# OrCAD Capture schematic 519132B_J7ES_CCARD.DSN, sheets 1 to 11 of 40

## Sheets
1 01.TITLE PAGE: title: J7ES CCARD; rev: A1; company: TEXAS INSTRUMENTS INCORPORATED; note: 519132; note: TIDEP-01020; note: Preliminary Information - Subject to change
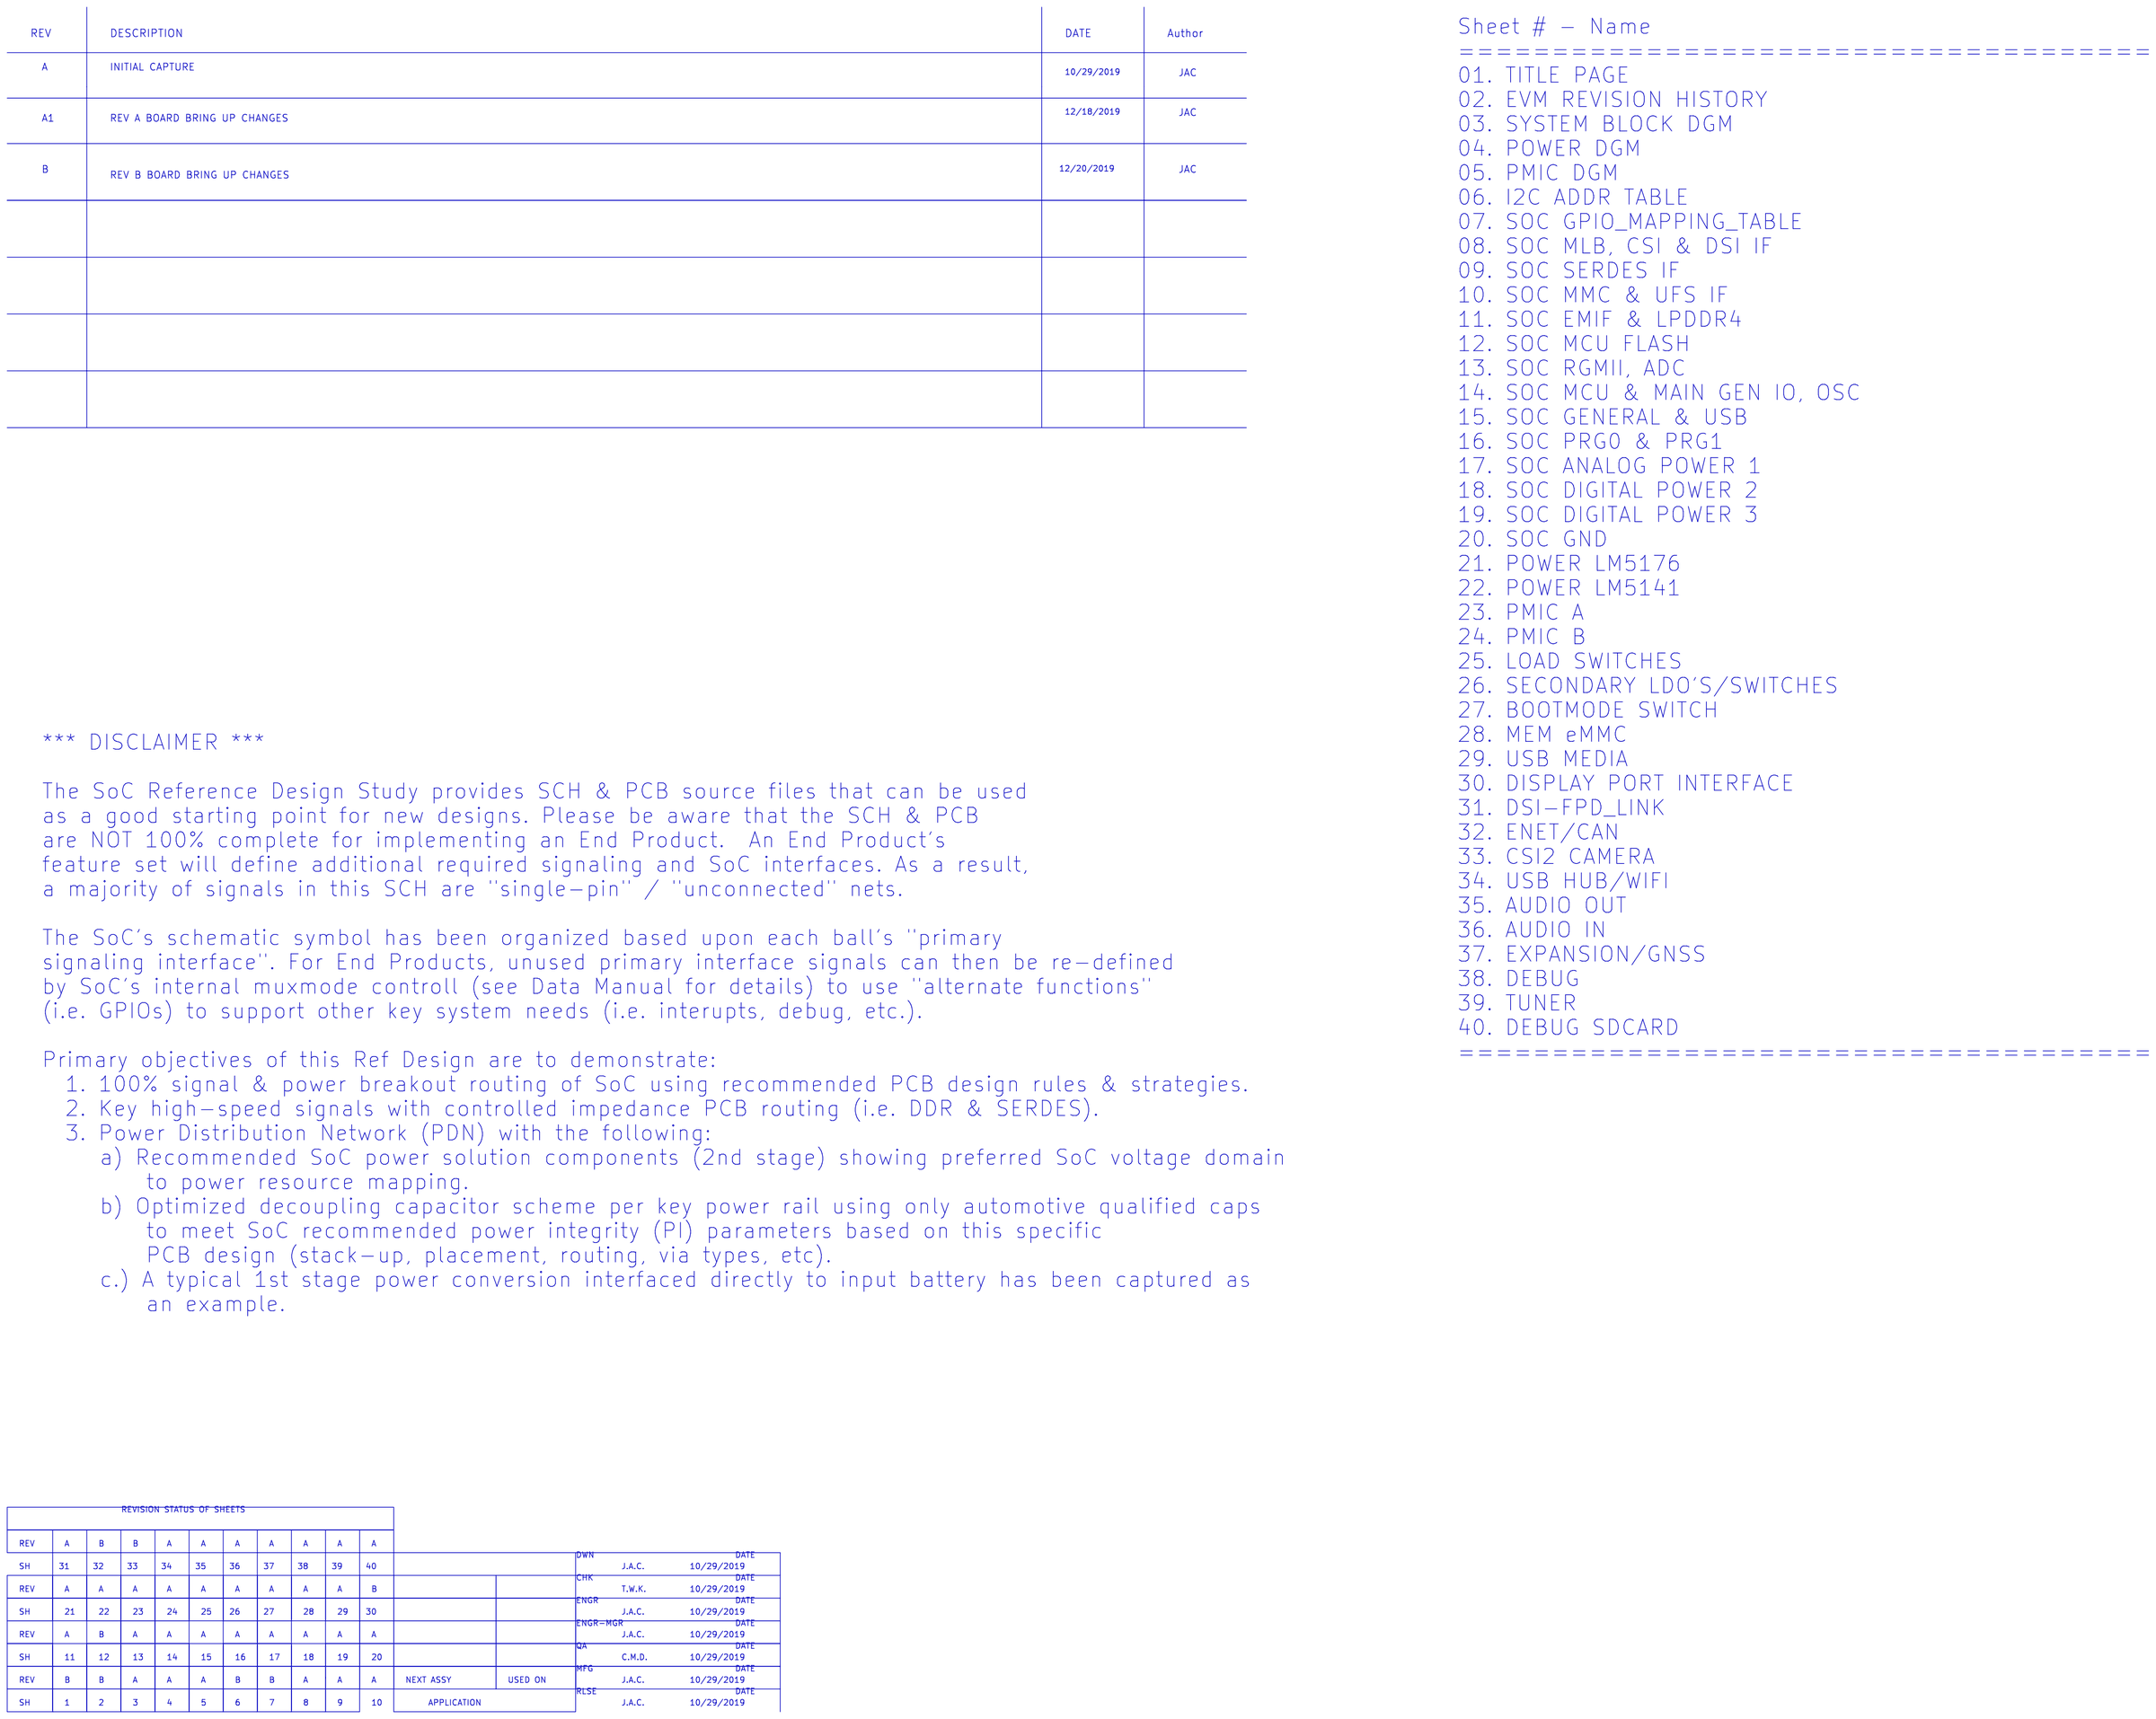
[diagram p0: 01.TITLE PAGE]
2 02. EVM REVISION HISTORY: rev: B
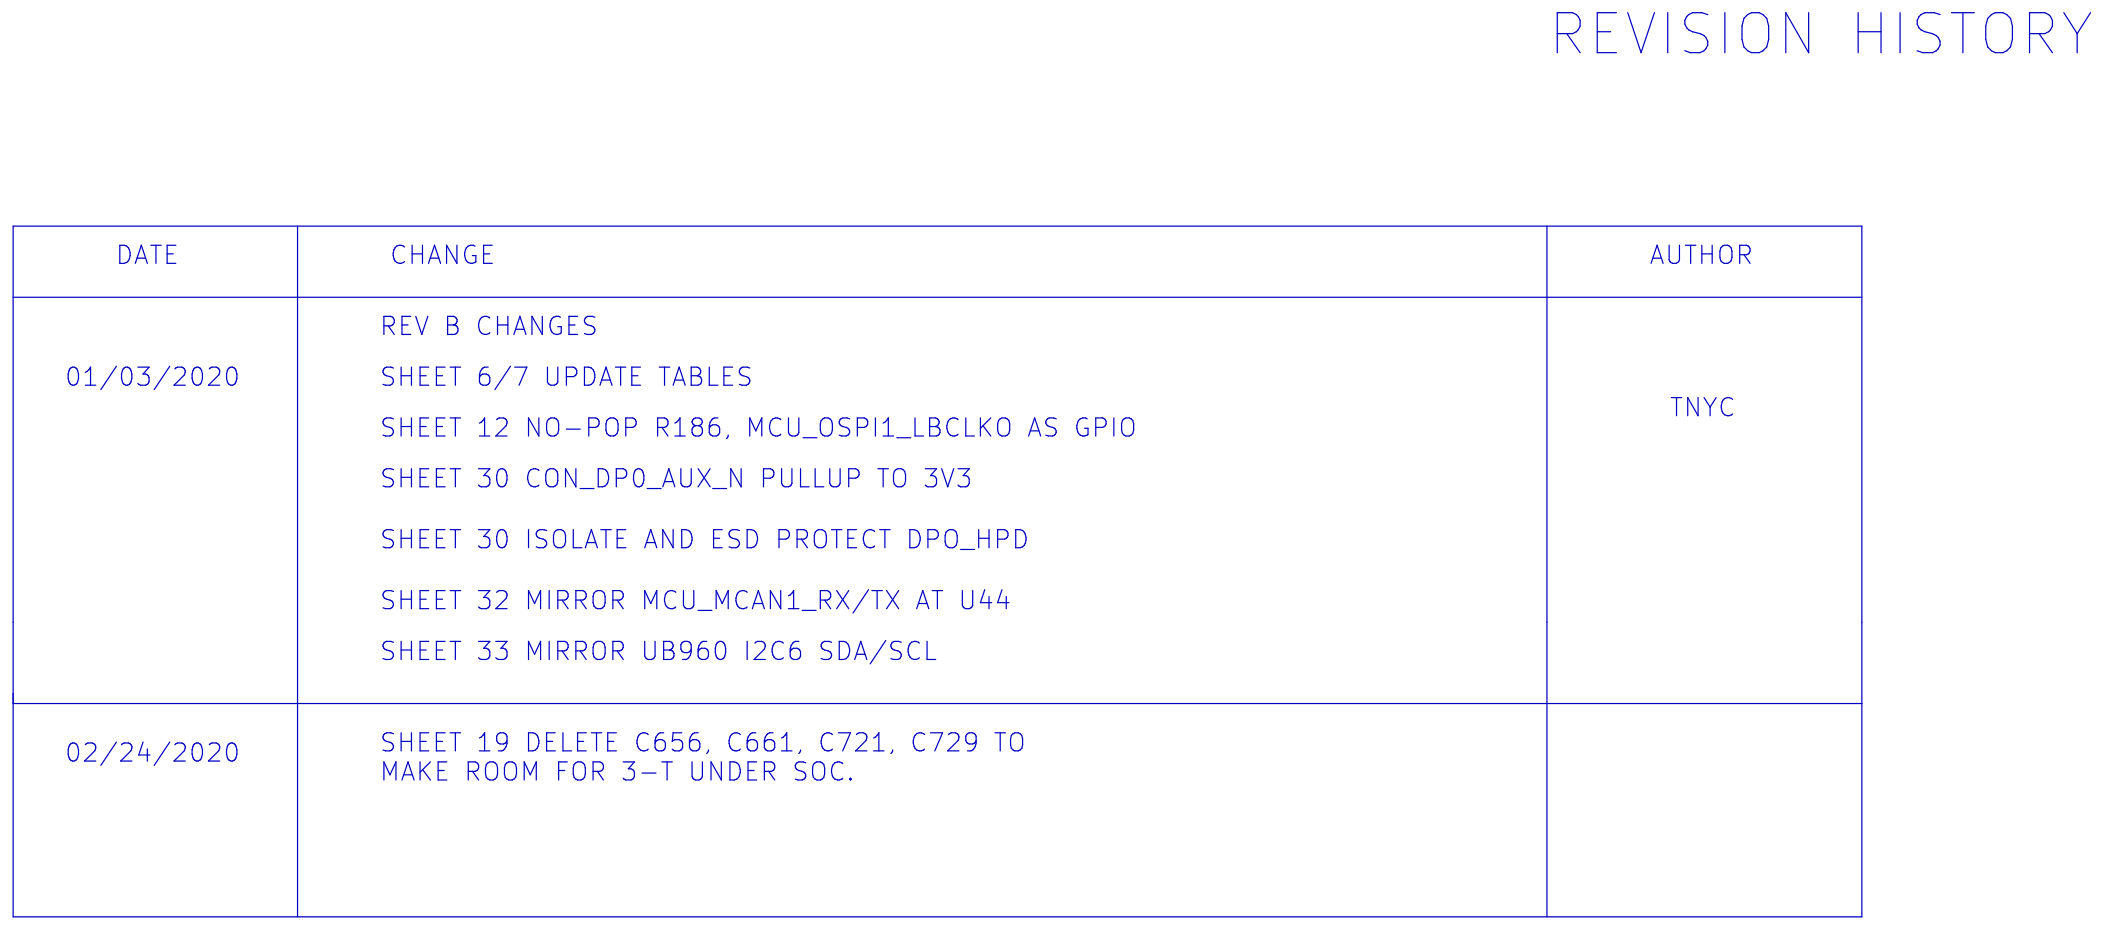
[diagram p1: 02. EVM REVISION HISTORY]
3 03. SYSTEM BLOCK DGM: rev: A
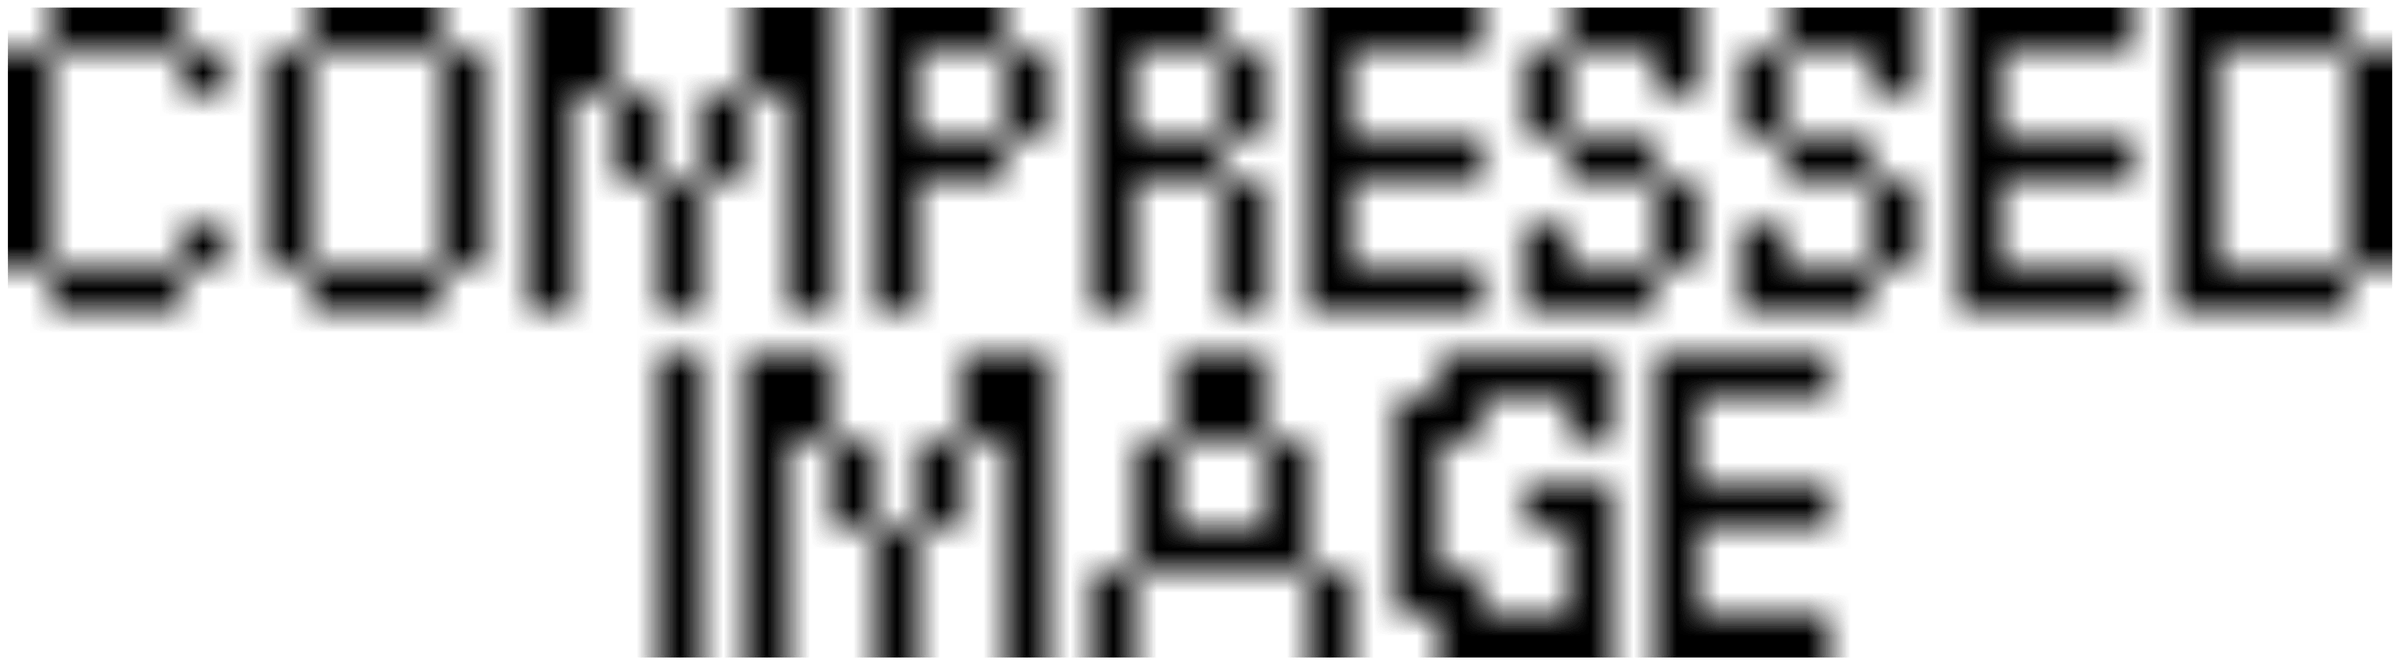
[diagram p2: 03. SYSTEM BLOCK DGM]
4 04. POWER DGM: rev: A
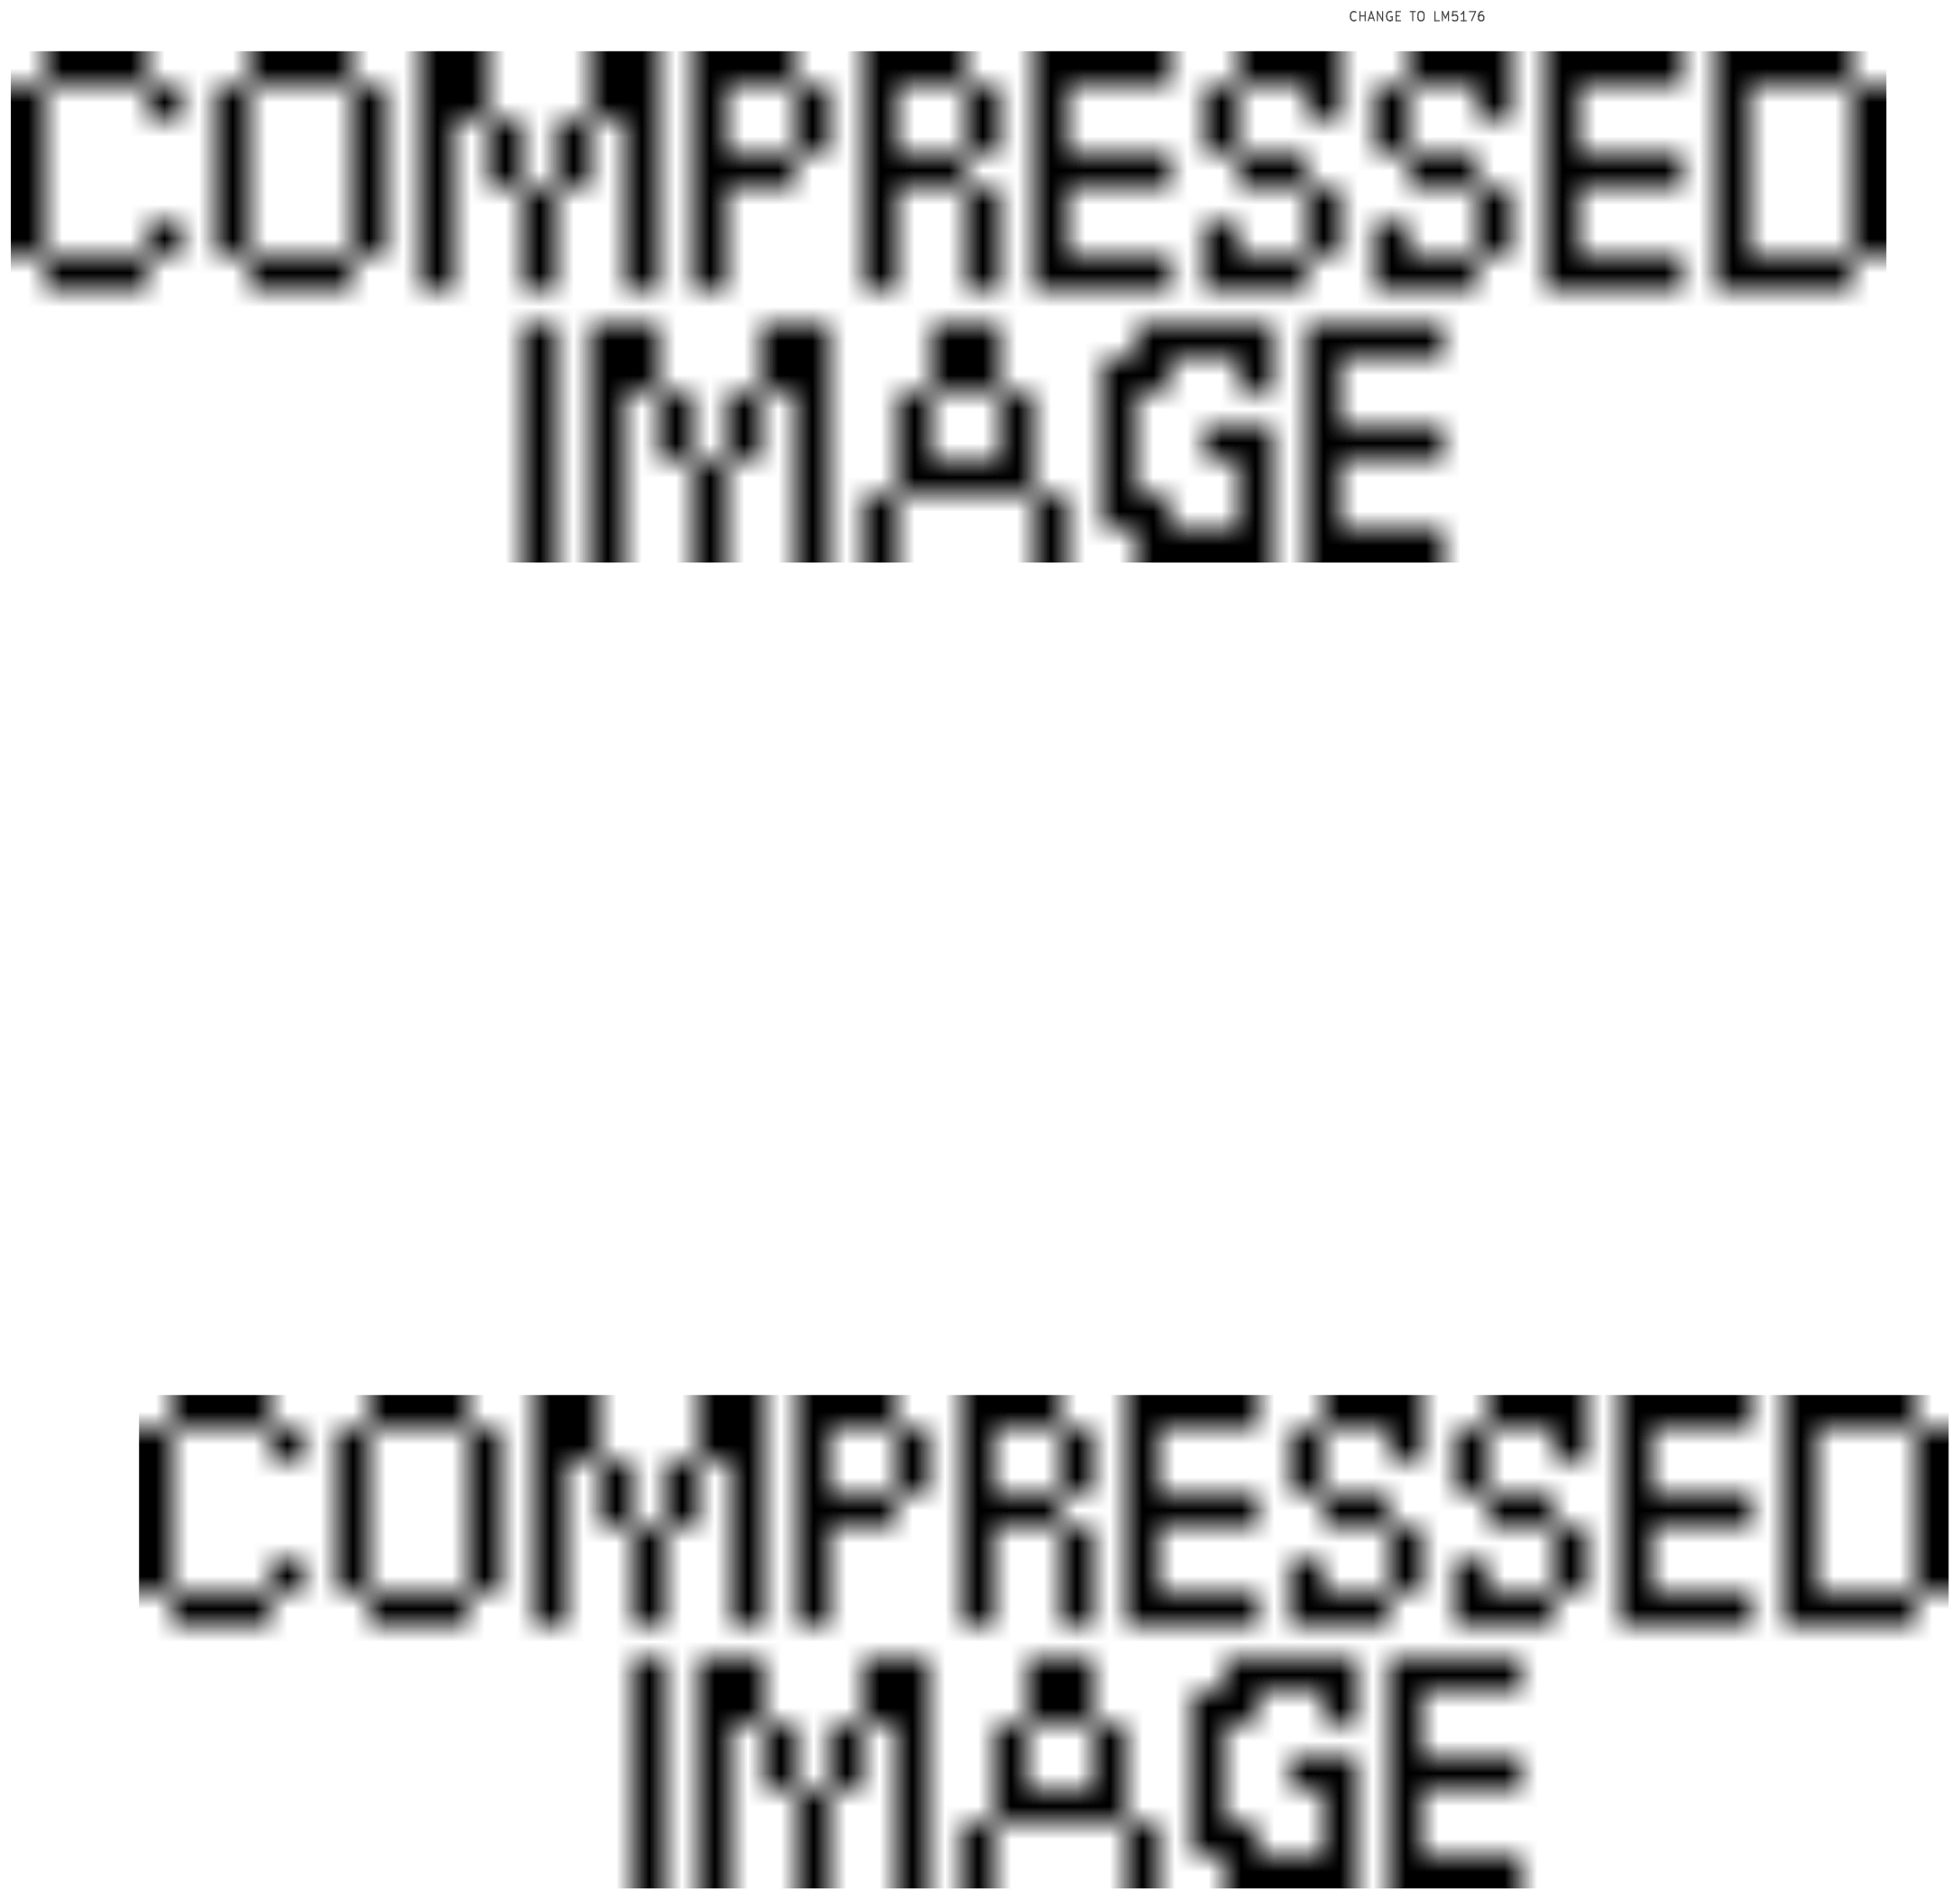
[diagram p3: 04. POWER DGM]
5 05. PMIC DGM: rev: A
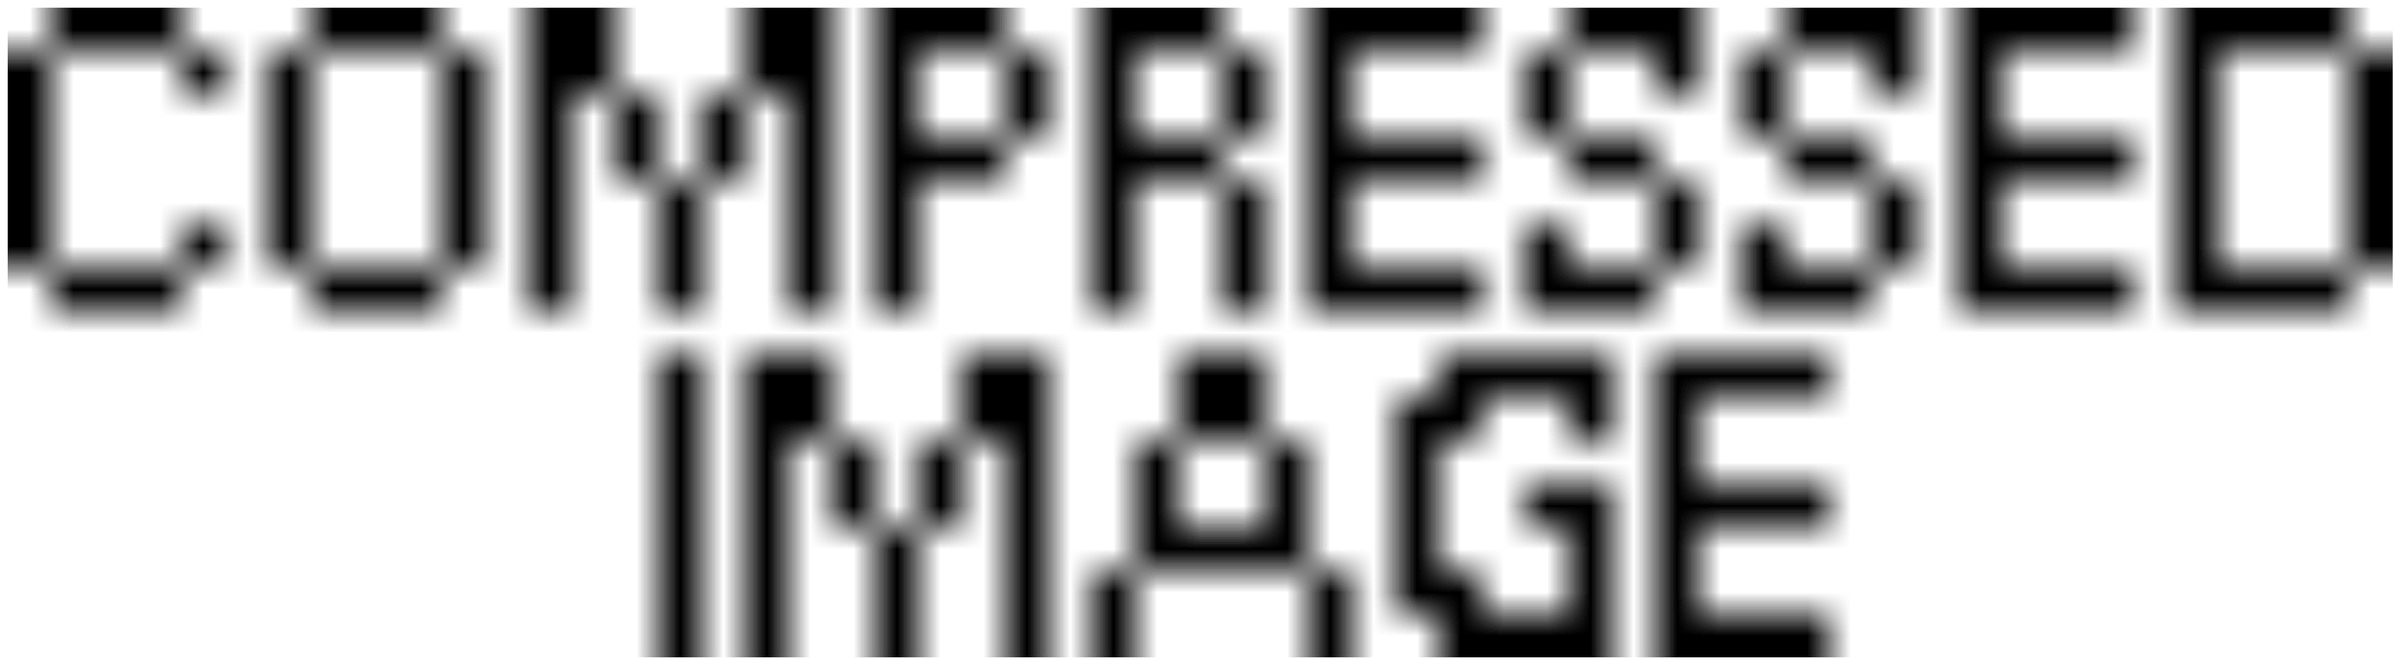
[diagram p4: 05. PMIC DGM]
6 06. I2C ADDR TABLE
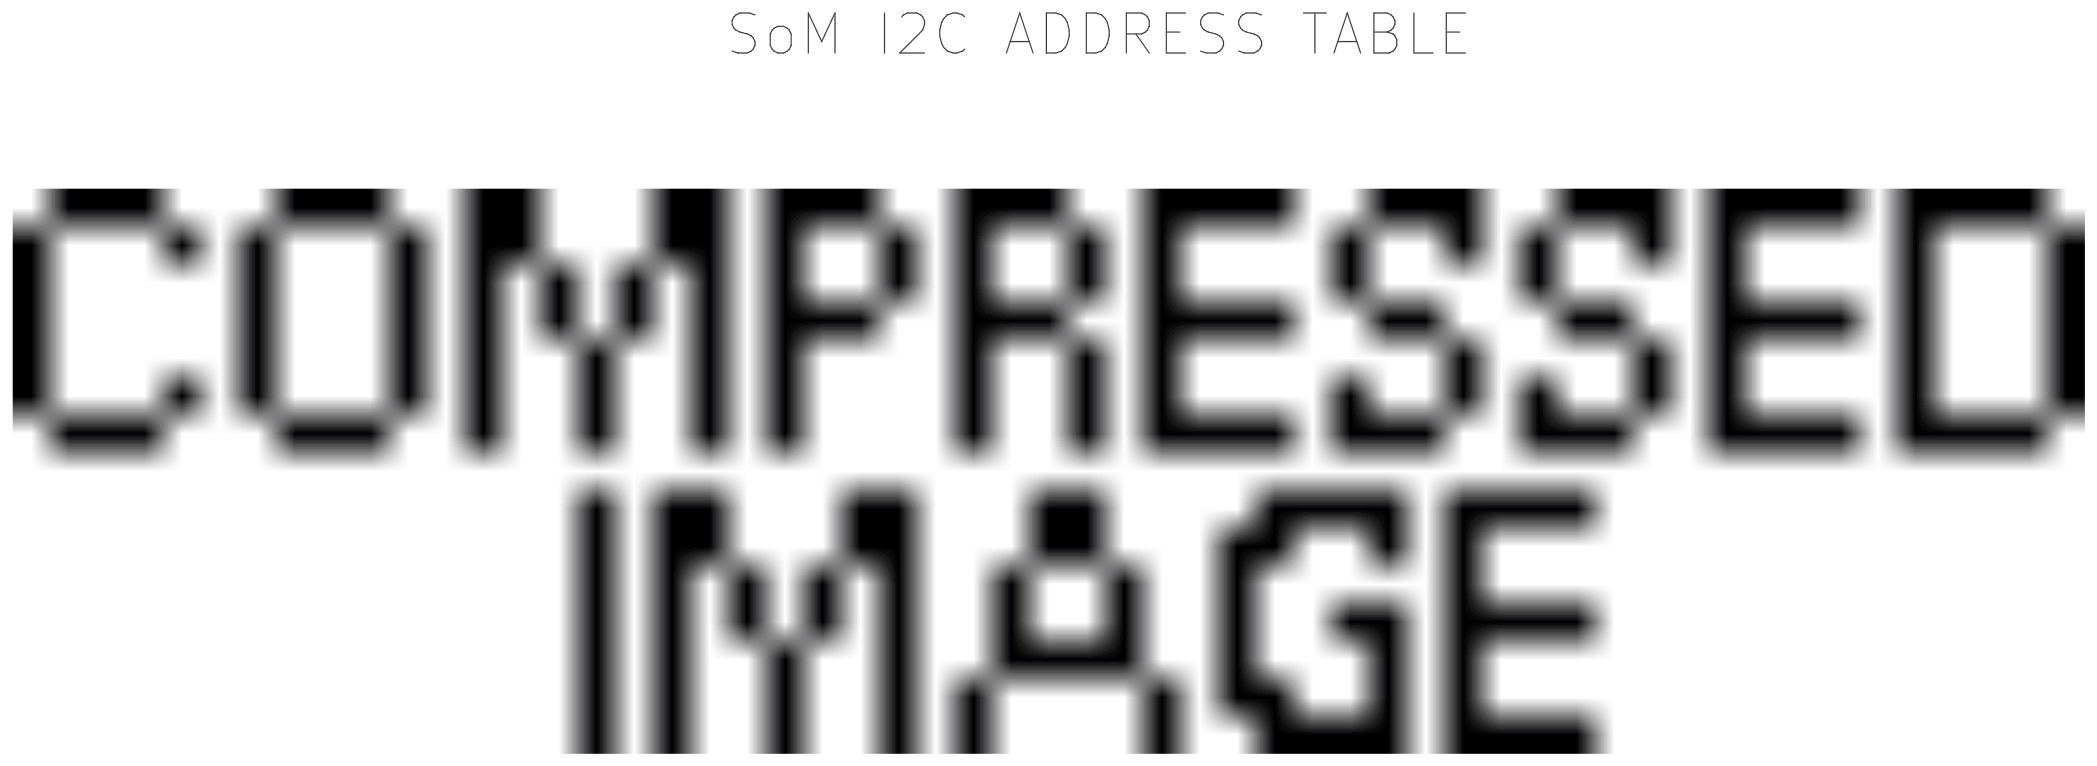
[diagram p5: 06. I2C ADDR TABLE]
7 07. SOC GPIO_MAPPING_TABLE
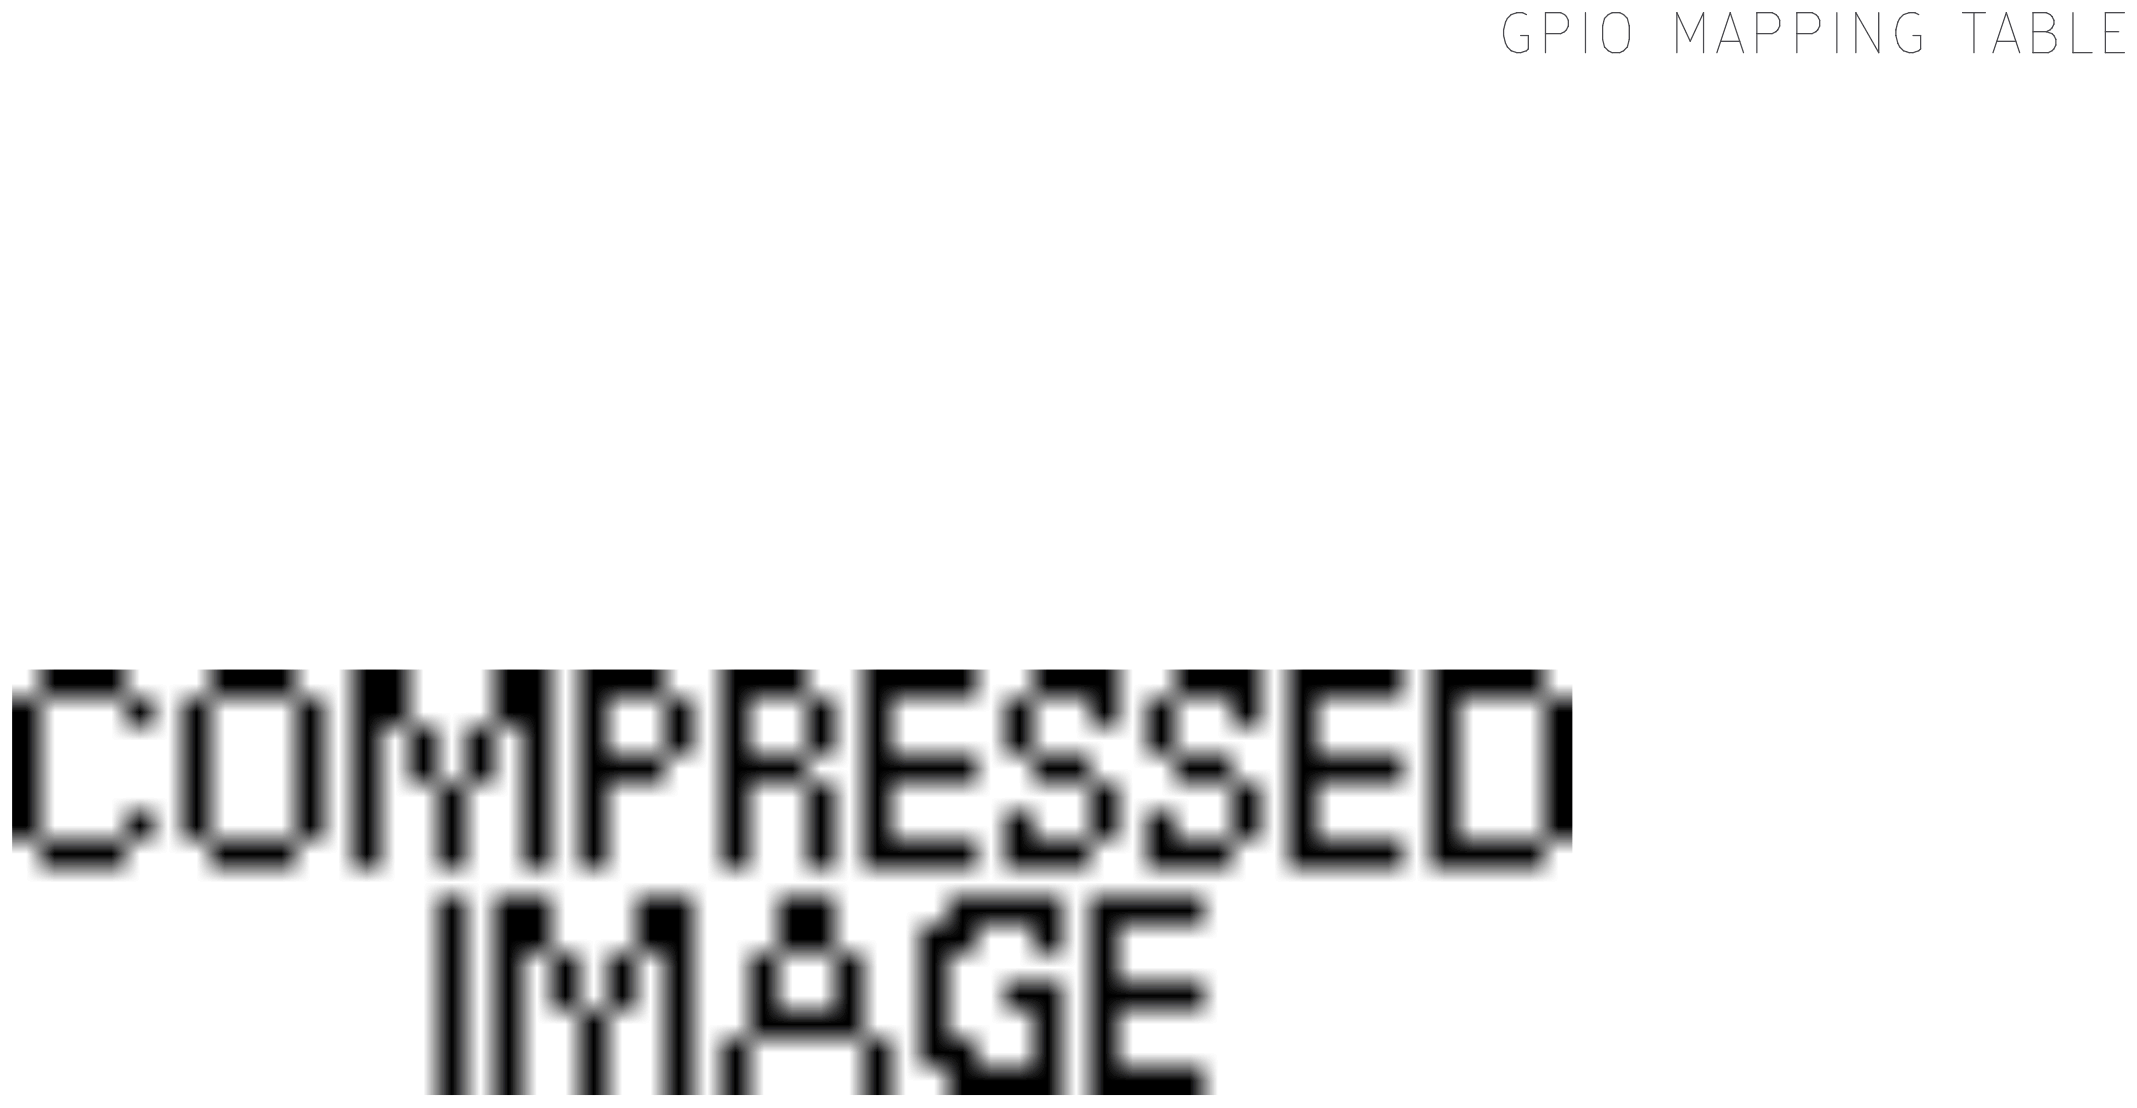
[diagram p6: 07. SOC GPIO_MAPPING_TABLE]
8 08. SOC MLB, CSI & DSI IF: size C; rev: A
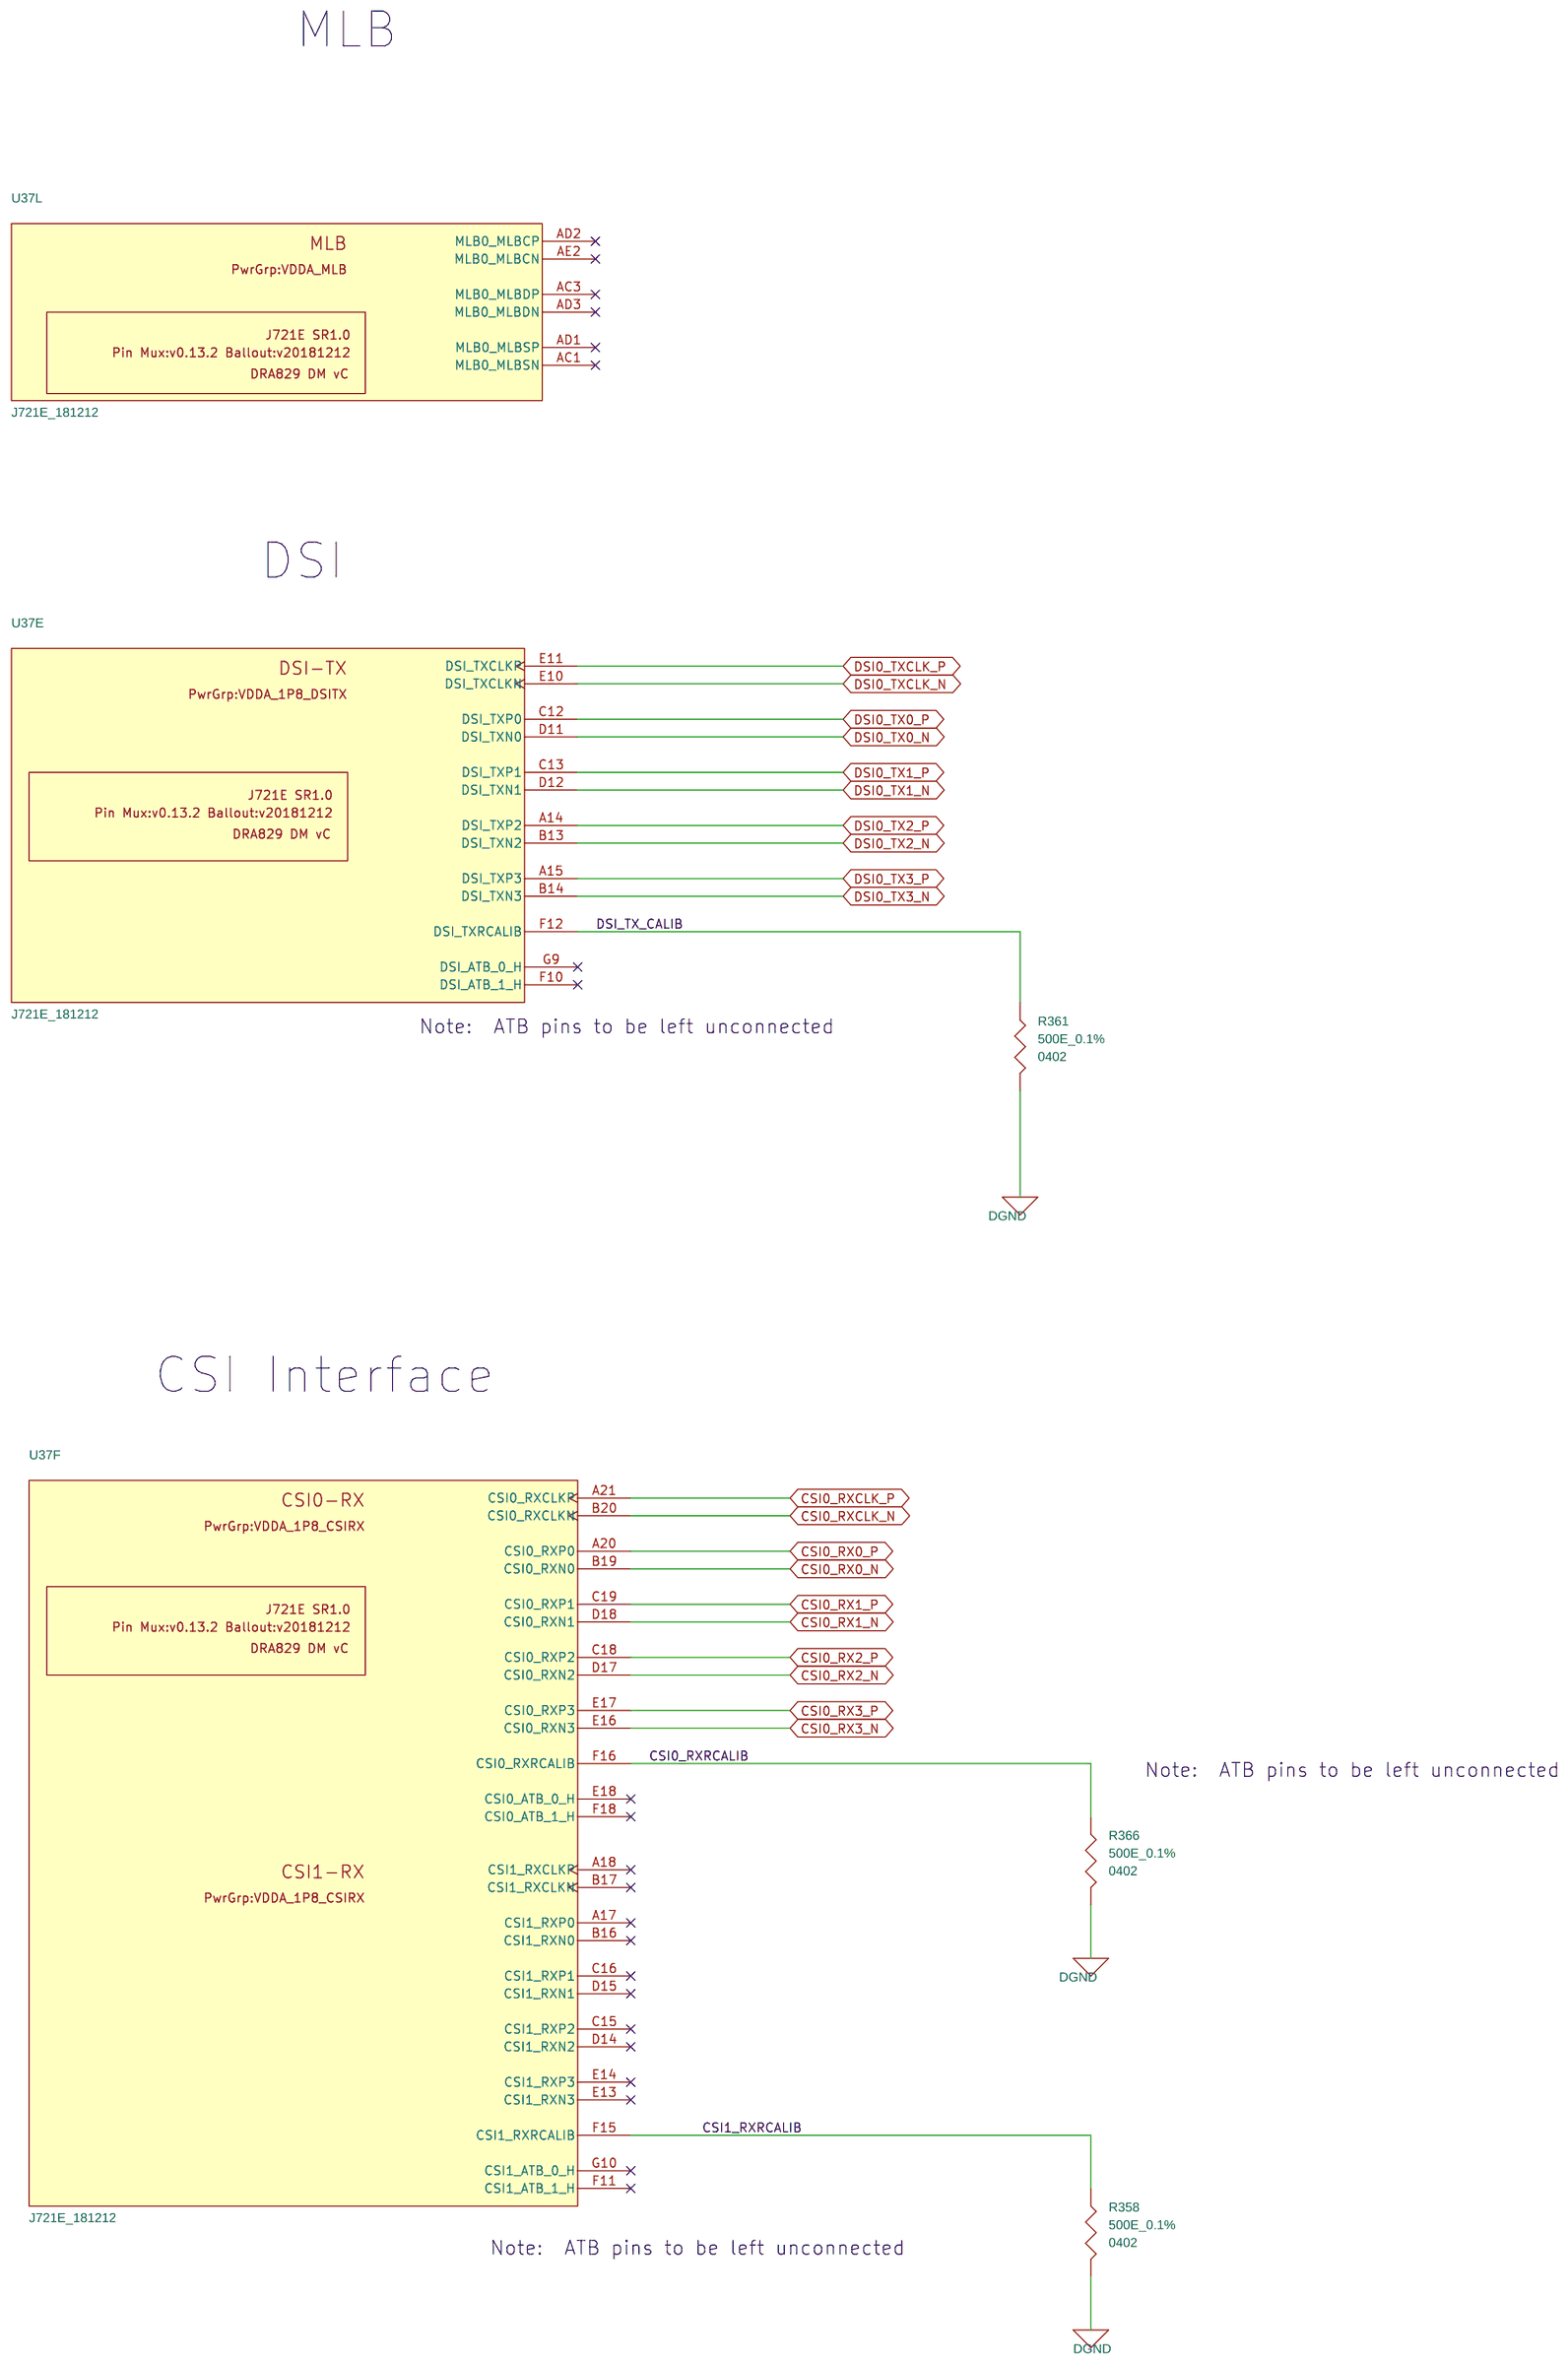
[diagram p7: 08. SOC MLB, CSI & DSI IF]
9 09. SOC SERDES IF: size C; rev: A
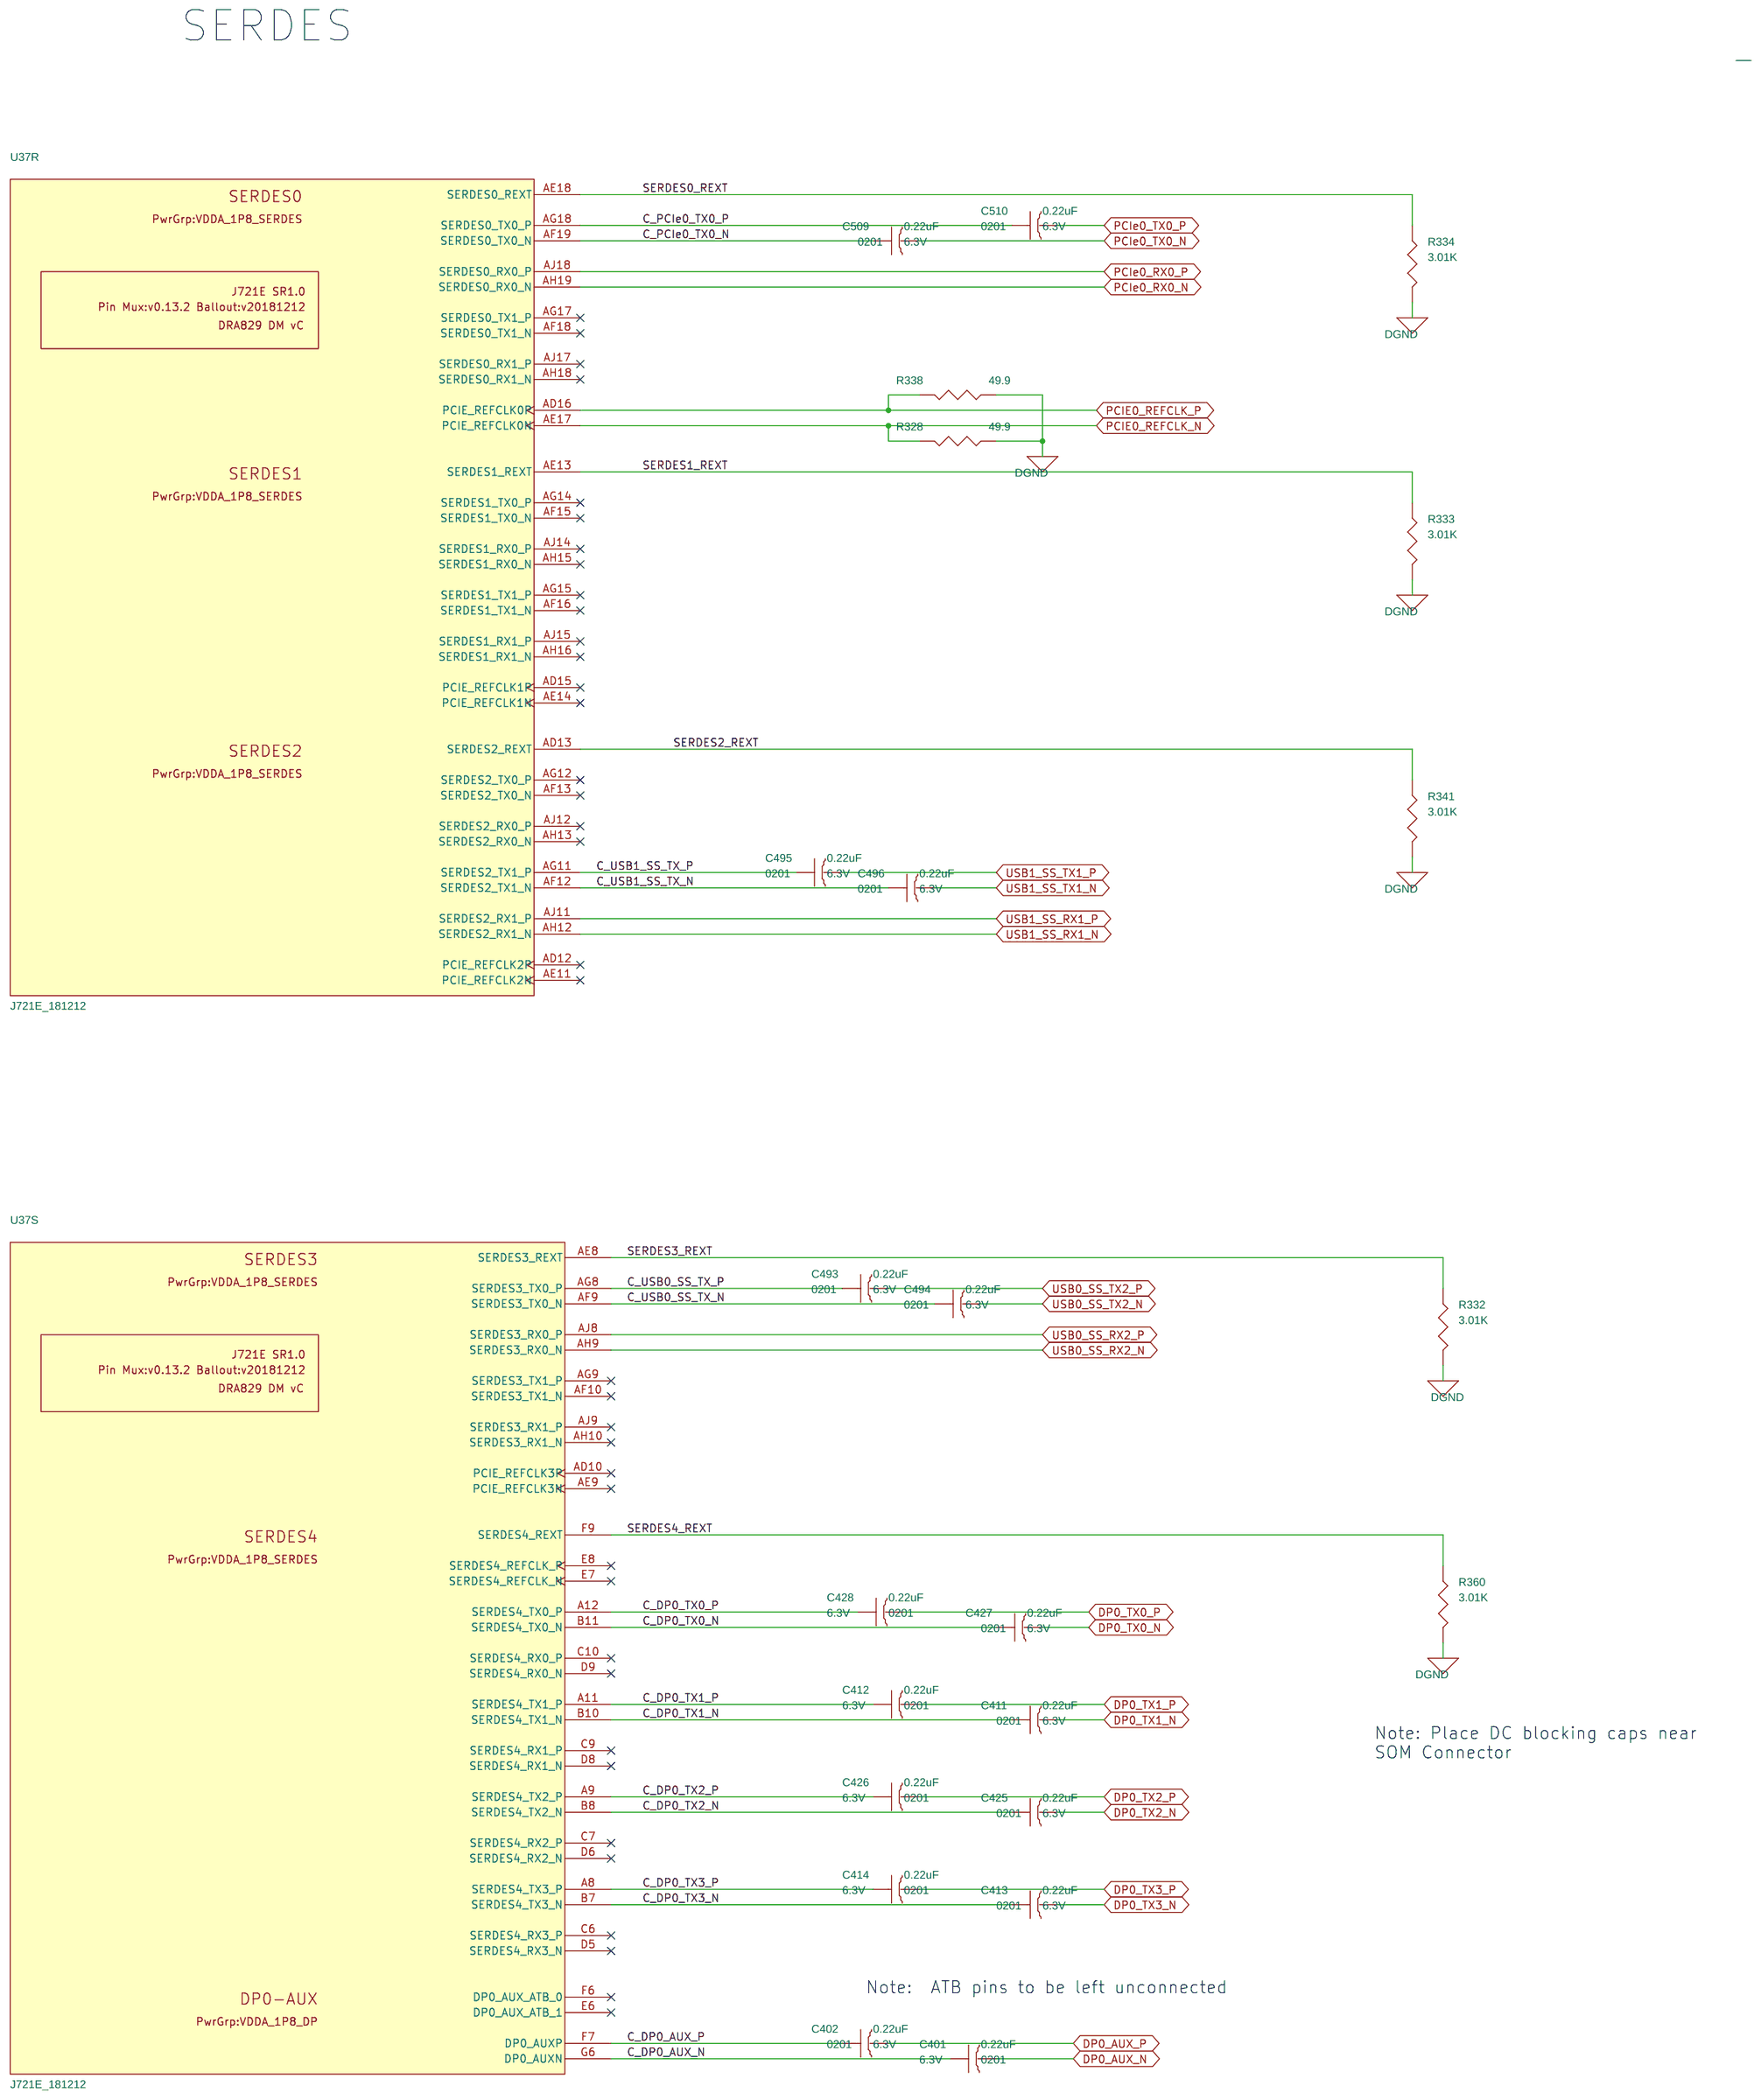
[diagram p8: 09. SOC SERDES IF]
10 10. SOC MMC & UFS IF: size C; rev: A
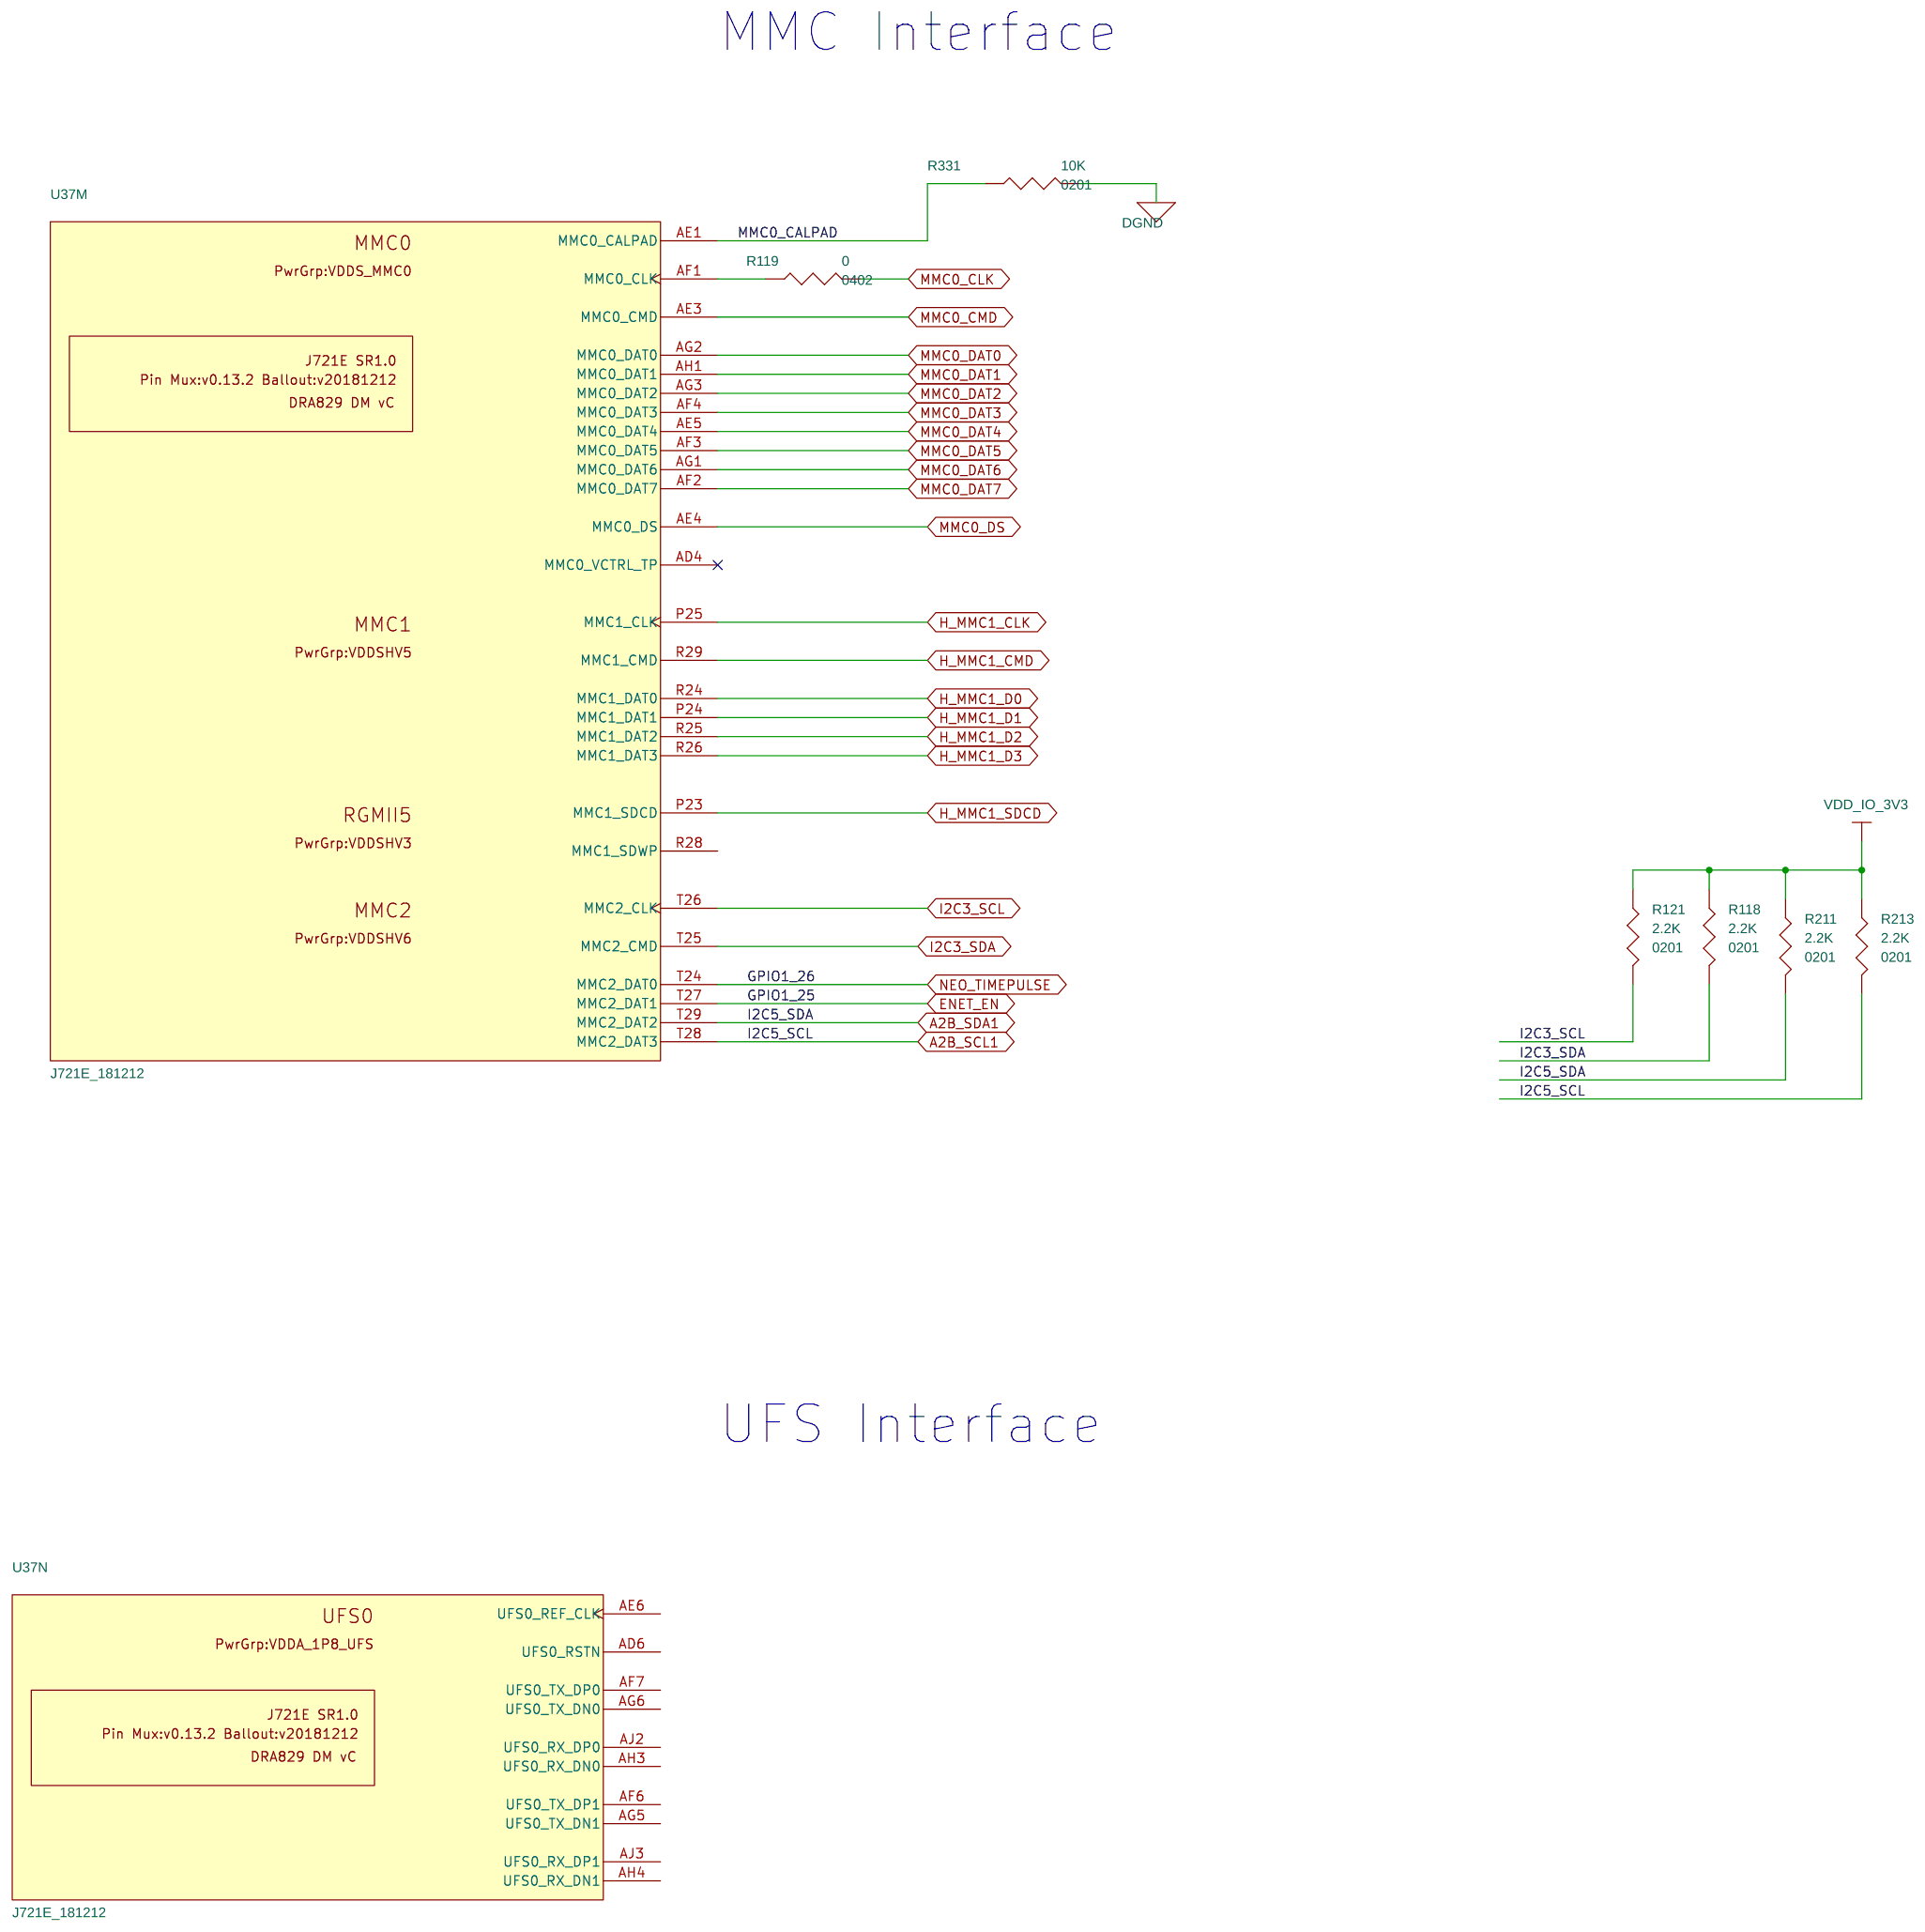
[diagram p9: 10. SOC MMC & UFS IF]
11 11. SOC EMIF & LPDDR4: size C; rev: A
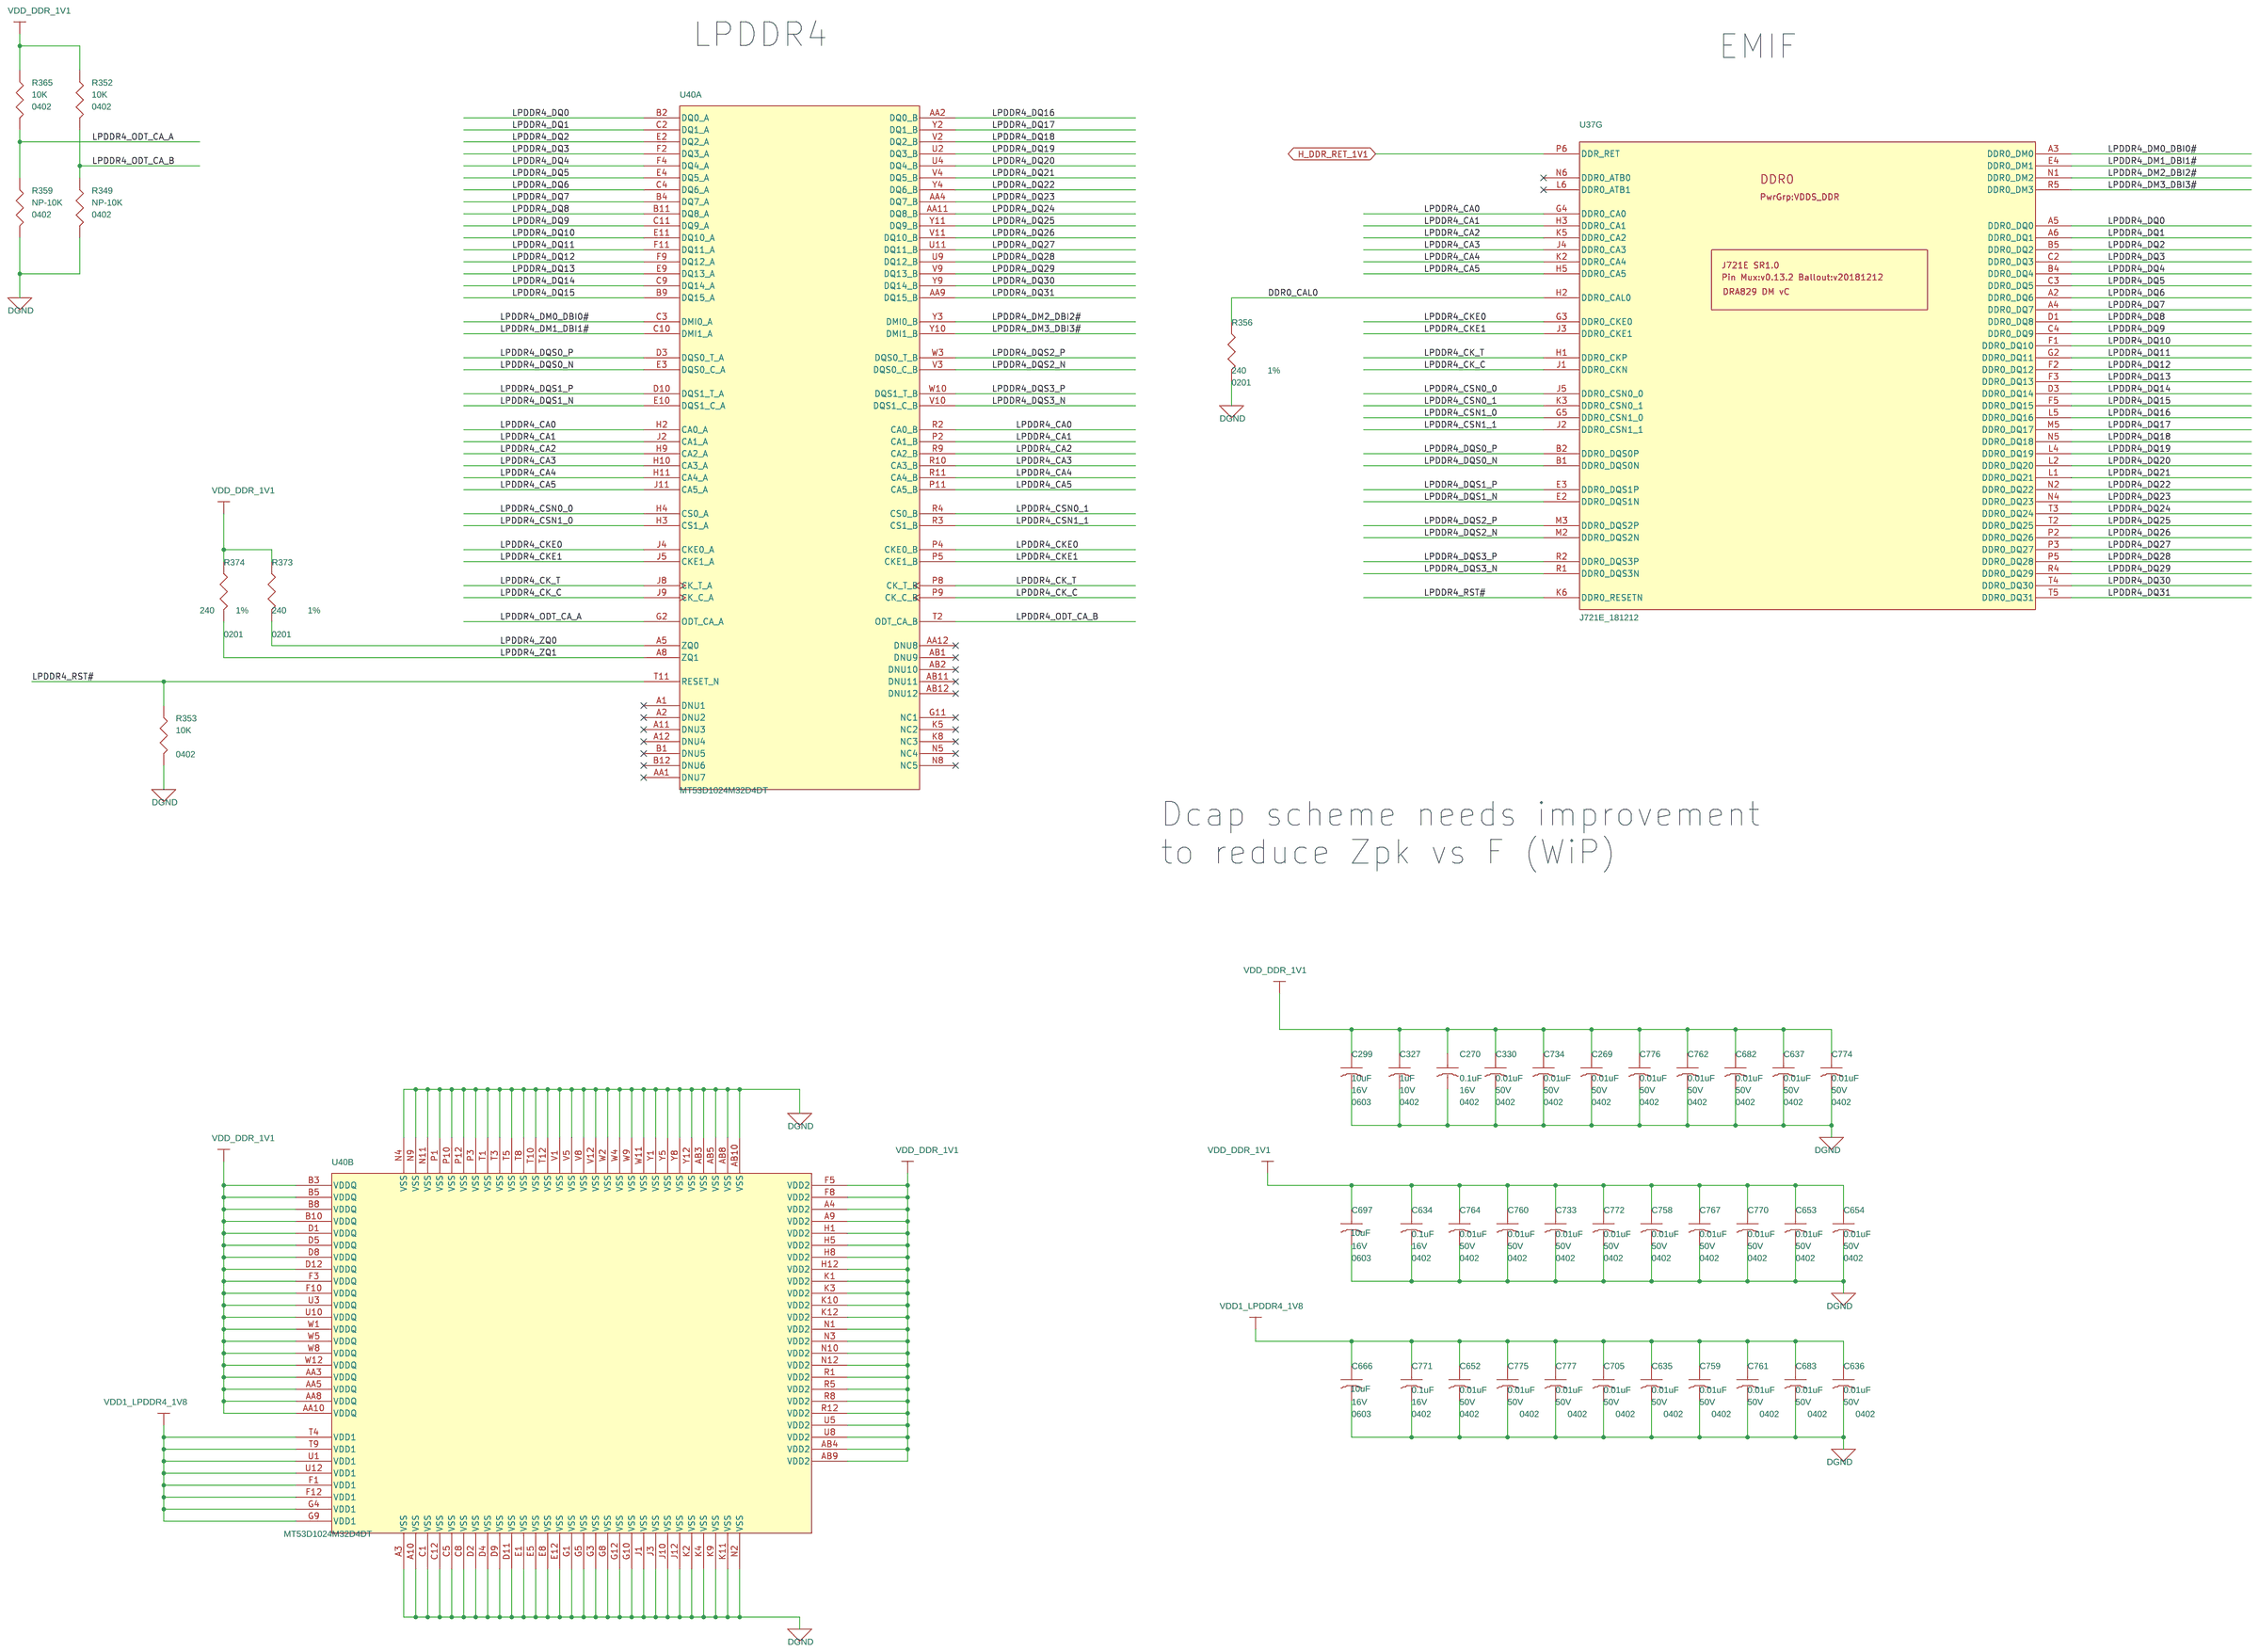
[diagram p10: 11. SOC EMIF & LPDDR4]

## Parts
sheet 08. SOC MLB, CSI & DSI IF
R358  500E_0.1%  [r402-25]
R361  500E_0.1%  [r402-25]
R366  500E_0.1%  [r402-25]
sheet 09. SOC SERDES IF
C401  0.22uF  [c201-6p6spc]
C402  0.22uF  [c201-6p6spc]
C411  0.22uF  [c201-6p6spc]
C412  0.22uF  [c201-6p6spc]
C413  0.22uF  [c201-6p6spc]
C414  0.22uF  [c201-6p6spc]
C425  0.22uF  [c201-6p6spc]
C426  0.22uF  [c201-6p6spc]
C427  0.22uF  [c201-6p6spc]
C428  0.22uF  [c201-6p6spc]
C493  0.22uF  [c201-6p6spc]
C494  0.22uF  [c201-6p6spc]
C495  0.22uF  [c201-6p6spc]
C496  0.22uF  [c201-6p6spc]
C509  0.22uF  [c201-6p6spc]
C510  0.22uF  [c201-6p6spc]
R328  49.9  [r402-25]
R332  3.01K  [r201-18p5x15]
R333  3.01K  [r201-18p5x15]
R334  3.01K  [r201-18p5x15]
R338  49.9  [r402-25]
R341  3.01K  [r201-18p5x15]
R360  3.01K  [r201-18p5x15]
sheet 10. SOC MMC & UFS IF
R118  2.2K  [r201-18p5x15]
R119  0  [r402-25]
R121  2.2K  [r201-18p5x15]
R211  2.2K  [r201-18p5x15]
R213  2.2K  [r201-18p5x15]
R331  10K  [r201-18p5x15]
sheet 11. SOC EMIF & LPDDR4
C269  0.01uF  [c402-25]
C270  0.1uF  [c402-25]
C299  10uF  [c603-35x45]
C327  1uF  [c402-25]
C330  0.01uF  [c402-25]
C634  0.1uF  [c402-25]
C635  0.01uF  [c402-25]
C636  0.01uF  [c402-25]
C637  0.01uF  [c402-25]
C652  0.01uF  [c402-25]
C653  0.01uF  [c402-25]
C654  0.01uF  [c402-25]
C666  10uF  [c603-35x45]
C682  0.01uF  [c402-25]
C683  0.01uF  [c402-25]
C697  10uF  [c603-35x45]
C705  0.01uF  [c402-25]
C733  0.01uF  [c402-25]
C734  0.01uF  [c402-25]
C758  0.01uF  [c402-25]
C759  0.01uF  [c402-25]
C760  0.01uF  [c402-25]
C761  0.01uF  [c402-25]
C762  0.01uF  [c402-25]
C764  0.01uF  [c402-25]
C767  0.01uF  [c402-25]
C770  0.01uF  [c402-25]
C771  0.1uF  [c402-25]
C772  0.01uF  [c402-25]
C774  0.01uF  [c402-25]
C775  0.01uF  [c402-25]
C776  0.01uF  [c402-25]
C777  0.01uF  [c402-25]
R349  NP-10K  [r402-25]
R352  10K  [r402-25]
R353  10K  [r402-25]
R356  240  [r201-18p5x15]
R359  NP-10K  [r402-25]
R365  10K  [r402-25]
R373  240  [r201-18p5x15]
R374  240  [r201-18p5x15]
U40  MT53D1024M32D4DT  [WFBGA200_MT53DDS_400X570_1]  (sections A,B)
sheet 16. SOC PRG0 & PRG1
U37  J721E_181212  [FCBGA827_31-49_950X950_2-8]  (sections A,B,C,D,E,F,G,H,I,J,K,L,M,N,O,P,Q,R,S,T,U,V,W)

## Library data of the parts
R358 R361 R366 = RESISTOR: RES 500E 1/20W 0.1% 0402; Chkd/date: MANIRAJA/190219; Crtd /date: ALVY/190219; Custom_Duty: 15%; Customs_HS_Code: 85332119; Distributor_name: DIGIKEY; Distributor_part_number: 541-1905-1-ND; Footprint Path: Y:\MIS_DATABASE\Library\ALTIUM_TOOL\PCB_FOOTPRINTS\Altium_Footprint_Lib.PcbLib; Height: 0.84MM; Library Path: Y:\MIS_DATABASE\Library\ALTIUM_TOOL\SCHEMATICS_PARTS\MS_DISCRETE_Library.schlib; Mfr_name: VISHAY; Mfr_part_number: PNM0402E5000BST1; Mistral Part No: 110019020003-R; Package: 0402; Part #: 105270-5001R; Part_type: RESISTORS\FIXED; Project: TI_J7ES_EVM_SOM; RoHS: RoHS; Temperature: -55°C+155°C; Tolerance: 0.1%; Voltage: NA; Wattage: 1/20W; Weight: NA; Datasheet: Y:\MIS_DATABASE\DATASHEETS\RESISTORS\PNM_VISHAY-SEP18.PDF
C401 C402 C411-C414 C425-C428 C493-C496 C509 C510 = CAP: CAP CERAMIC 0.22uF 6.3V 10% X6S AUTO 0201; Chkd/date: MANIRAJA/220219; Crtd /date: ALVY/220219; Custom_Duty: 15%; Customs_HS_Code: 85322990; Distributor_name: DIGIKEY; Distributor_part_number: 490-12230-1-ND; Footprint Path: Y:\MIS_DATABASE\Library\ALTIUM_TOOL\PCB_FOOTPRINTS\Altium_Footprint_Lib.PcbLib; Height: 0.33MM; Library Path: Y:\MIS_DATABASE\Library\ALTIUM_TOOL\SCHEMATICS_PARTS\MS_DISCRETE_Library.schlib; Mfr_name: MURATA; Mfr_part_number: GRT033C80J224KE01D; Mistral Part No: 120019020011-R; Package: 0201; Part #: 105321-1220R; Part_type: CAPACITORS\CERAMIC; Project: TI_J7ES_EVM_SOM; RoHS: RoHS; Temperature: -55°C+105°C; Tolerance: 10%; Voltage: 6.3V; Wattage: NA; Weight: 0.17mg; Datasheet: Y:\MIS_DATABASE\DATASHEETS\CAPACITORS\MURATA-GCM-SER.PDF
R328 R338 = RESISTOR: RES 100E 1/10W 1% 0402; Assembly_Instruction: DNI; Chkd/date: MANIRAJA/130617; Crtd /date: JEBRAN/040715; Custom_Duty: 15%; Customs_HS_Code: 85332119; Distributor_name: DIGIKEY; Distributor_part_number: P100LCT-ND; Footprint Path: Y:\MIS_DATABASE\Library\ALTIUM_TOOL\PCB_FOOTPRINTS\Altium_Footprint_Lib.PcbLib; Height: 0.40MM; Library Path: Y:\MIS_DATABASE\Library\ALTIUM_TOOL\SCHEMATICS_PARTS\MS_DISCRETE_Library.schlib; Mfr_name: PANASONIC-ECG; Mfr_part_number: ERJ-2RKF1000X; Mistral Part No: 110018020036-R; Package: 0402; Part #: 102145-4990R; Part_type: RESISTORS\FIXED; Project: CYPHY_FVB; RoHS: RoHS; Temperature: -55°C+155°C; Tolerance: 1%; Voltage: NA; Wattage: 1/10W; Weight: 0.8mg; Datasheet: Y:\MIS_DATABASE\DATASHEETS\RESISTORS\PAN-ERJSER_NOV17.PDF
R332-R334 R341 R360 = RESISTOR: RES 3.01K 1/20W 1% 0201; Chkd/date: MANIRAJA/160519; Crtd /date: ALVY/160519; Custom_Duty: 15%; Customs_HS_Code: 85332119; Distributor_name: DIGIKEY; Distributor_part_number: P122916CT-ND; Footprint Path: Y:\MIS_DATABASE\Library\ALTIUM_TOOL\PCB_FOOTPRINTS\Altium_Footprint_Lib.PcbLib; Height: 0.26MM; Library Path: Y:\MIS_DATABASE\Library\ALTIUM_TOOL\SCHEMATICS_PARTS\MS_DISCRETE_Library.schlib; Mfr_name: PANASONIC-ECG; Mfr_part_number: ERJ-1GNF3011C; Mistral Part No: 110015080044-R; Package: 0201; Part #: 103413-3012R; Part_type: RESISTORS\FIXED; Project: J7ES_SOM_DUAL-LEO_PMIC; RoHS: RoHS; Temperature: -55°C+125°C; Tolerance: 1%; Voltage: NA; Wattage: 1/20W; Weight: 0.15mg; Datasheet: Y:\MIS_DATABASE\DATASHEETS\RESISTORS\PAN-ERJSER_NOV17.PDF
R118 R121 R211 R213 = RESISTOR: RES 2.2K 1/20W 5% 0201; Chkd/date: MANIRAJA/050517; Crtd /date: MANIRAJA/050517; Custom_Duty: 15%; Customs_HS_Code: 85332119; Distributor_name: DIGIKEY; Distributor_part_number: 311-2.2KNCT-ND; Footprint Path: Y:\MIS_DATABASE\Library\ALTIUM_TOOL\PCB_FOOTPRINTS\Altium_Footprint_Lib.PcbLib; Height: 0.26MM; Library Path: Y:\MIS_DATABASE\Library\ALTIUM_TOOL\SCHEMATICS_PARTS\MS_DISCRETE_Library.schlib; Mfr_name: YAGEO AMERICA; Mfr_part_number: RC0201JR-072K2L; Mistral Part No: 110009030427-R; Package: 0201; Part #: 103158-2202R; Part_type: RESISTORS\FIXED; Project: GOLDEN-I LITE; RoHS: RoHS; Temperature: -55°C+125°C; Tolerance: 5%; Voltage: NA; Wattage: 1/20W; Weight: 0.17mg; Datasheet: Y:\MIS_DATABASE\DATASHEETS\RESISTORS\RCXXXXL-SER_MAR18.PDF
R119 = RESISTOR: RES 22E 1/16W 1% 0402; Chkd/date: SUHAS/290910; Crtd /date: MAZHAR/090909; Cust_part_number: 4700-80047E; Custom_Duty: 15%; Customs_HS_Code: 85332119; Distributor_name: DIGIKEY; Distributor_part_number: 311-22.0LRCT-ND; Footprint Path: Y:\MIS_DATABASE\Library\ALTIUM_TOOL\PCB_FOOTPRINTS\Altium_Footprint_Lib.PcbLib; Height: 0.40MM; Library Path: Y:\MIS_DATABASE\Library\ALTIUM_TOOL\SCHEMATICS_PARTS\MS_DISCRETE_Library.schlib; Mfr_name: YAGEO AMERICA; Mfr_part_number: RC0402FR-0722RL; Mistral Part No: 110009090004-R; Package: 0402; Part #: 101370-0001R; Part_type: RESISTORS\FIXED; Project: VMEFMCD; RoHS: RoHS; Temperature: -55°C+155°C; Tolerance: 1%; Voltage: NA; Wattage: 1/16W; Weight: 0.65mg; Datasheet: Y:\MIS_DATABASE\DATASHEETS\RESISTORS\RCXXXXL-SER_MAR18.PDF
R331 = RESISTOR: RES 10K 1/20W 1% 0201; Chkd/date: MANIRAJA/080519; Crtd /date: ALVY/080519; Custom_Duty: 15%; Customs_HS_Code: 85332119; Distributor_name: DIGIKEY; Distributor_part_number: 1276-3670-1-ND; Footprint Path: Y:\MIS_DATABASE\Library\ALTIUM_TOOL\PCB_FOOTPRINTS\Altium_Footprint_Lib.PcbLib; Height: 0.26MM; Library Path: Y:\MIS_DATABASE\Library\ALTIUM_TOOL\SCHEMATICS_PARTS\MS_DISCRETE_Library.schlib; Mfr_name: SAMSUNG; Mfr_part_number: RC0603F103CS; Mistral Part No: 110011040018-R; Package: 0201; Part #: 103413-1003R; Part_type: RESISTORS\FIXED; Project: BRUKER_SD820_COMMONDO; RoHS: RoHS; Temperature: -55°C+125°C; Tolerance: 1%; Voltage: NA; Wattage: 1/20W; Weight: 0.15mg; Datasheet: Y:\MIS_DATABASE\DATASHEETS\RESISTORS\SAMSUNG_RC-SER.PDF
C269 C330 C635-C637 C652-C654 C682 C683 C705 C733 C734 C758-C762 C764 C767 C770 C772 C774-C777 = CAP: CAP CERAMIC 0.01uF 50V 10% X7R 0402; Chkd/date: SHREESHAIL/301105; Crtd /date: MAZHAR/040505; Custom_Duty: 15%; Customs_HS_Code: 85322990; Distributor_name: DIGIKEY; Distributor_part_number: 399-3066-1-ND; Footprint Path: Y:\MIS_DATABASE\Library\ALTIUM_TOOL\PCB_FOOTPRINTS\Altium_Footprint_Lib.PcbLib; Height: 0.55MM; Library Path: Y:\MIS_DATABASE\Library\ALTIUM_TOOL\SCHEMATICS_PARTS\MS_DISCRETE_Library.schlib; Mfr_name: KEMET; Mfr_part_number: C0402C103K5RACTU; Mistral Part No: 120009030025-R; Package: 0402; Part #: 104725-1101R; Part_type: CAPACITORS\CERAMIC; Project: G4_SVGA; RoHS: RoHS; Temperature: -55°C+125°C; Tolerance: 10%; Voltage: 50V; Wattage: NA; Weight: 0.65mg; Datasheet: Y:\MIS_DATABASE\DATASHEETS\CAPACITORS\KEMET-C-X7R.PDF
C270 C634 C771 = CAP: CAP CERAMIC 0.1uF 16V 5% X7R AUTO 0402; Chkd/date: MANIRAJA/241018; Crtd /date: ALVY/241018; Custom_Duty: 15%; Customs_HS_Code: 85322990; Distributor_name: DIGIKEY; Distributor_part_number: 490-16433-1-ND; Footprint Path: Y:\MIS_DATABASE\Library\ALTIUM_TOOL\PCB_FOOTPRINTS\Altium_Footprint_Lib.PcbLib; Height: 0.55MM; Library Path: Y:\MIS_DATABASE\Library\ALTIUM_TOOL\SCHEMATICS_PARTS\MS_DISCRETE_Library.schlib; Mfr_name: MURATA; Mfr_part_number: GCM155R71C104JA55D; Mistral Part No: 120018100055-R; Package: 0402; Part #: 104446-1100R; Part_type: CAPACITORS\CERAMIC; Project: TI_J7ES_EVM_CP; RoHS: RoHS; Temperature: -55°C+125°C; Tolerance: 5%; Voltage: 16V; Wattage: NA; Weight: 6mg; Datasheet: Y:\MIS_DATABASE\DATASHEETS\CAPACITORS\GCM155R71C104JA55D.PDF
C299 C666 C697 = CAP: CAP CERAMIC 10uF 16V 20% X6S 0603; Chkd/date: VASANTHA/170117; Crtd /date: VASANTHA/170117; Custom_Duty: 15%; Customs_HS_Code: 85322990; Distributor_name: DIGIKEY; Distributor_part_number: 490-7198-1-ND; Footprint Path: Y:\MIS_DATABASE\Library\ALTIUM_TOOL\PCB_FOOTPRINTS\Altium_Footprint_Lib.PcbLib; Height: 0.90MM; Library Path: Y:\MIS_DATABASE\Library\ALTIUM_TOOL\SCHEMATICS_PARTS\MS_DISCRETE_Library.schlib; Mfr_name: MURATA; Mfr_part_number: GRM188C81C106MA73D; Mistral Part No: 120017010004-R; Package: 0603; Part #: 105312-0101R; Part_type: CAPACITORS\CERAMIC; Project: TRMM_SMART-M_PS; RoHS: RoHS; Temperature: -55°C+105°C; Tolerance: 20%; Voltage: 16V; Wattage: NA; Weight: 6.3mg; Datasheet: Y:\MIS_DATABASE\DATASHEETS\CAPACITORS\MURATA-GXX-SER_NOV17.PDF
C327 = CAP: CAP CERAMIC 1uF 10V 10% X7S AUTO 0402; Chkd/date: MANIRAJA/100918; Crtd /date: ALVY/100918; Custom_Duty: 15%; Customs_HS_Code: 85322990; Distributor_name: DIGIKEY; Distributor_part_number: 490-13409-1-ND; Footprint Path: Y:\MIS_DATABASE\Library\ALTIUM_TOOL\PCB_FOOTPRINTS\Altium_Footprint_Lib.PcbLib; Height: 0.70MM; Library Path: Y:\MIS_DATABASE\Library\ALTIUM_TOOL\SCHEMATICS_PARTS\MS_DISCRETE_Library.schlib; Mfr_name: MURATA; Mfr_part_number: GCM155C71A105KE38D; Mistral Part No: 120018090021-R; Package: 0402; Part #: 104911-0100R; Part_type: CAPACITORS\CERAMIC; Project: SMART-M_SCRIPTALK_PB; RoHS: RoHS; Temperature: -55°C+125°C; Tolerance: 10%; Voltage: 10V; Wattage: NA; Weight: 6mg; Datasheet: Y:\MIS_DATABASE\DATASHEETS\CAPACITORS\MURATA-GCM-SER.PDF
R349 R359 = RESISTOR: RES 10K 1/16W 1% 0402; Assembly_Instruction: DNI; Chkd/date: VASANTHA/201216; Crtd /date: GEETHA/290506; Custom_Duty: 15%; Customs_HS_Code: 85332119; Distributor_name: DIGIKEY; Distributor_part_number: 311-10.0KLRTR-ND; Footprint Path: Y:\MIS_DATABASE\Library\ALTIUM_TOOL\PCB_FOOTPRINTS\Altium_Footprint_Lib.PcbLib; Height: 0.40MM; Library Path: Y:\MIS_DATABASE\Library\ALTIUM_TOOL\SCHEMATICS_PARTS\MS_DISCRETE_Library.schlib; Mfr_name: YAGEO AMERICA; Mfr_part_number: RC0402FR-0710KL; Mistral Part No: 110015090015-R; Package: 0402; Part #: R0402-NOPOP; Part_type: RESISTORS\FIXED; Project: VOCERA; RoHS: RoHS; Temperature: -55°C+155°C; Tolerance: 1%; Voltage: NA; Wattage: 1/16W; Weight: 0.65mg; Datasheet: Y:\MIS_DATABASE\DATASHEETS\RESISTORS\RCXXXXL-SER_MAR18.PDF
R352 R365 = RESISTOR: RES 10K 1/16W 1% 0402; Chkd/date: VASANTHA/201216; Crtd /date: GEETHA/290506; Custom_Duty: 15%; Customs_HS_Code: 85332119; Distributor_name: DIGIKEY; Distributor_part_number: 311-10.0KLRTR-ND; Footprint Path: Y:\MIS_DATABASE\Library\ALTIUM_TOOL\PCB_FOOTPRINTS\Altium_Footprint_Lib.PcbLib; Height: 0.40MM; Library Path: Y:\MIS_DATABASE\Library\ALTIUM_TOOL\SCHEMATICS_PARTS\MS_DISCRETE_Library.schlib; Mfr_name: YAGEO AMERICA; Mfr_part_number: RC0402FR-0710KL; Mistral Part No: 110015090015-R; Package: 0402; Part #: 102145-1003R; Part_type: RESISTORS\FIXED; Project: VOCERA; RoHS: RoHS; Temperature: -55°C+155°C; Tolerance: 1%; Voltage: NA; Wattage: 1/16W; Weight: 0.65mg; Datasheet: Y:\MIS_DATABASE\DATASHEETS\RESISTORS\RCXXXXL-SER_MAR18.PDF
R353 = RESISTOR: RES 10K 1/16W 1% 0402; Assembly_Instruction: DNI; Chkd/date: VASANTHA/201216; Crtd /date: GEETHA/290506; Custom_Duty: 15%; Customs_HS_Code: 85332119; Distributor_name: DIGIKEY; Distributor_part_number: 311-10.0KLRTR-ND; Footprint Path: Y:\MIS_DATABASE\Library\ALTIUM_TOOL\PCB_FOOTPRINTS\Altium_Footprint_Lib.PcbLib; Height: 0.40MM; Library Path: Y:\MIS_DATABASE\Library\ALTIUM_TOOL\SCHEMATICS_PARTS\MS_DISCRETE_Library.schlib; Mfr_name: YAGEO AMERICA; Mfr_part_number: RC0402FR-0710KL; Mistral Part No: 110015090015-R; Package: 0402; Part #: 102145-1003R; Part_type: RESISTORS\FIXED; Project: VOCERA; RoHS: RoHS; Temperature: -55°C+155°C; Tolerance: 1%; Voltage: NA; Wattage: 1/16W; Weight: 0.65mg; Datasheet: Y:\MIS_DATABASE\DATASHEETS\RESISTORS\RCXXXXL-SER_MAR18.PDF
R356 R373 R374 = RESISTOR: RES 240E 1/20W 1% 0201; Chkd/date: VASANTHA/251116; Crtd /date: MANIRAJA/241116; Custom_Duty: 15%; Customs_HS_Code: 85332119; Distributor_name: DIGIKEY; Distributor_part_number: YAG2528CT-ND; Footprint Path: Y:\MIS_DATABASE\Library\ALTIUM_TOOL\PCB_FOOTPRINTS\Altium_Footprint_Lib.PcbLib; Height: 0.26MM; Library Path: Y:\MIS_DATABASE\Library\ALTIUM_TOOL\SCHEMATICS_PARTS\MS_DISCRETE_Library.schlib; Mfr_name: YAGEO AMERICA; Mfr_part_number: RC0201FR-07240RL; Mistral Part No: 110016110007-R; Package: 0201; Part #: 103413-2401R; Part_type: RESISTORS\FIXED; Project: ALL_DATA_NANO_SOM; RoHS: RoHS; Temperature: -55°C+125°C; Tolerance: 1%; Voltage: NA; Wattage: 1/20W; Weight: 0.17mg; Datasheet: Y:\MIS_DATABASE\DATASHEETS\RESISTORS\RCXXXXL-SER_MAR18.PDF
U40 = MT53D1024M32D4DT_VFBGA200: IC 32Gb AUTOMOTIVE LPDDR4 SDRAM VFBGA200; Chkd/date: MANIRAJA/250618; Crtd /date: ALVY/220618; Custom_Duty: 15%; Customs_HS_Code: 85423100; Distributor_name: DIGIKEY; Distributor_part_number: MT53D1024M32D4DT-046AAT:D-ND; Footprint Path: Y:\MIS_DATABASE\Library\ALTIUM_TOOL\PCB_FOOTPRINTS\Altium_Footprint_Lib.PcbLib; Height: 0.95MM; Library Path: Y:\MIS_DATABASE\Library\ALTIUM_TOOL\SCHEMATICS_PARTS\MS_MISCMEMORY_Library.schlib; Mfr_name: MICRON; Mfr_part_number: MT53D1024M32D4DT-046 AAT:D; Mistral Part No: 141118060006-R; Package: VFBGA200; Part #: 105325-0001R; Part_type: ICS\DIGITAL\MEMORY; Project: TI_J7_SVB-DUT; RoHS: RoHS; Temperature: -40°C+105°C; Tolerance: NA; Voltage: NA; Wattage: NA; Weight: NA; Datasheet: Y:\MIS_DATABASE\DATASHEETS\ICS\MEMORY\MT53DXXX-SER.PDF
U37 = J7ES-EVM_BGA827_0: IC J7ES MICROPROCESSOR BGA827; Chkd/date: MANIRAJA/151018; Crtd /date: MANIRAJA/151018; Custom_Duty: 15%; Customs_HS_Code: 85423100; Distributor_name: NA; Distributor_part_number: NA; Footprint Path: Y:\MIS_DATABASE\Library\ALTIUM_TOOL\PCB_FOOTPRINTS\Altium_Footprint_Lib.PcbLib; Height: 2.79MM; Library Path: Y:\MIS_DATABASE\Library\ALTIUM_TOOL\SCHEMATICS_PARTS\MS_MICROPROCESSOR_Library.schlib; Library Ref: J7ES-EVM_BGA827; Mfr_name: TEXAS INSTRUMENTS; Mfr_part_number: J7ES_EVM; Mistral Part No: 141218060001; Package: BGA827; Part #: 105271-0001R-TI; Part_type: ICS\DIGITAL\MICROPROCESSOR; Project: TI_J7ES_EVM_CP; RoHS: NA; Temperature: NA; Tolerance: NA; Voltage: NA; Wattage: NA; Weight: NA; Datasheet: Y:\MIS_DATABASE\DATASHEETS\ICS\DIGITAL\MICROCONTROLLER\J7ES.PDF

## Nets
DGND: C269.2 C270.2 C299.2 C327.2 C330.2 C634.2 C635.2 C636.2 C637.2 C652.2 C653.2 C654.2 C666.2 C682.2 C683.2 C697.2 C705.2 C733.2 C734.2 C758.2 C759.2 C760.2 C761.2 C762.2 C764.2 C767.2 C770.2 C771.2 C772.2 C774.2 C775.2 C776.2 C777.2 R328.2 R331.1 R332.2 R333.2 R334.2 R338.2 R341.2 R349.2 R353.2 R356.2 R358.2 R359.2 R360.2 R361.2 R366.2 U40.A3(VSS) U40.A10(VSS) U40.AB3(VSS) U40.AB5(VSS) U40.AB8(VSS) U40.AB10(VSS) U40.C1(VSS) U40.C5(VSS) U40.C8(VSS) U40.C12(VSS) U40.D2(VSS) U40.D4(VSS) U40.D9(VSS) U40.D11(VSS) U40.E1(VSS) U40.E5(VSS) U40.E8(VSS) U40.E12(VSS) U40.G1(VSS) U40.G3(VSS) U40.G5(VSS) U40.G8(VSS) U40.G10(VSS) U40.G12(VSS) U40.J1(VSS) U40.J3(VSS) U40.J10(VSS) U40.J12(VSS) U40.K2(VSS) U40.K4(VSS) U40.K9(VSS) U40.K11(VSS) U40.N2(VSS) U40.N4(VSS) U40.N9(VSS) U40.N11(VSS) U40.P1(VSS) U40.P3(VSS) U40.P10(VSS) U40.P12(VSS) U40.T1(VSS) U40.T3(VSS) U40.T5(VSS) U40.T8(VSS) U40.T10(VSS) U40.T12(VSS) U40.V1(VSS) U40.V5(VSS) U40.V8(VSS) U40.V12(VSS) U40.W2(VSS) U40.W4(VSS) U40.W9(VSS) U40.W11(VSS) U40.Y1(VSS) U40.Y5(VSS) U40.Y8(VSS) U40.Y12(VSS) ; also on sheet 12 13 14 15 17 18 19 20 21 22 23 24 25 26 27 28 29 30 31 32 33 34 35 36 37 38 39 40
VDD1_LPDDR4_1V8: C635.1 C636.1 C652.1 C666.1 C683.1 C705.1 C759.1 C761.1 C771.1 C775.1 C777.1 U40.F1(VDD1) U40.F12(VDD1) U40.G4(VDD1) U40.G9(VDD1) U40.T4(VDD1) U40.T9(VDD1) U40.U1(VDD1) U40.U12(VDD1) ; also on sheet 23
VDD_DDR_1V1: C269.1 C270.1 C299.1 C327.1 C330.1 C634.1 C637.1 C653.1 C654.1 C682.1 C697.1 C733.1 C734.1 C758.1 C760.1 C762.1 C764.1 C767.1 C770.1 C772.1 C774.1 C776.1 R352.1 R365.1 R373.1 R374.1 U40.A4(VDD2) U40.A9(VDD2) U40.AA3(VDDQ) U40.AA5(VDDQ) U40.AA8(VDDQ) U40.AA10(VDDQ) U40.AB4(VDD2) U40.AB9(VDD2) U40.B3(VDDQ) U40.B5(VDDQ) U40.B8(VDDQ) U40.B10(VDDQ) U40.D1(VDDQ) U40.D5(VDDQ) U40.D8(VDDQ) U40.D12(VDDQ) U40.F3(VDDQ) U40.F5(VDD2) U40.F8(VDD2) U40.F10(VDDQ) U40.H1(VDD2) U40.H5(VDD2) U40.H8(VDD2) U40.H12(VDD2) U40.K1(VDD2) U40.K3(VDD2) U40.K10(VDD2) U40.K12(VDD2) U40.N1(VDD2) U40.N3(VDD2) U40.N10(VDD2) U40.N12(VDD2) U40.R1(VDD2) U40.R5(VDD2) U40.R8(VDD2) U40.R12(VDD2) U40.U3(VDDQ) U40.U5(VDD2) U40.U8(VDD2) U40.U10(VDDQ) U40.W1(VDDQ) U40.W5(VDDQ) U40.W8(VDDQ) U40.W12(VDDQ) ; also on sheet 19 23 24
VDD_IO_3V3: R118.1 R121.1 R211.1 R213.1 ; also on sheet 15 16 18 21 25 26 27 28 29 30 31 32 34 35 36 37 38 39 40
A2B_SCL1: R213.2 U37.T28(MMC2_DAT3) ; also on sheet 39
A2B_SDA1: R211.2 U37.T29(MMC2_DAT2) ; also on sheet 39
C_DP0_AUX_N: C401.1 U37.G6(DP0_AUXN)
C_DP0_AUX_P: C402.1 U37.F7(DP0_AUXP)
C_DP0_TX0_N: C427.1 U37.B11(SERDES4_TX0_N)
C_DP0_TX0_P: C428.1 U37.A12(SERDES4_TX0_P)
C_DP0_TX1_N: C411.1 U37.B10(SERDES4_TX1_N)
C_DP0_TX1_P: C412.1 U37.A11(SERDES4_TX1_P)
C_DP0_TX2_N: C425.1 U37.B8(SERDES4_TX2_N)
C_DP0_TX2_P: C426.1 U37.A9(SERDES4_TX2_P)
C_DP0_TX3_N: C413.1 U37.B7(SERDES4_TX3_N)
C_DP0_TX3_P: C414.1 U37.A8(SERDES4_TX3_P)
C_PCIe0_TX0_N: C509.1 U37.AF19(SERDES0_TX0_N)
C_PCIe0_TX0_P: C510.1 U37.AG18(SERDES0_TX0_P)
C_USB0_SS_TX_N: C494.1 U37.AF9(SERDES3_TX0_N)
C_USB0_SS_TX_P: C493.1 U37.AG8(SERDES3_TX0_P)
C_USB1_SS_TX_N: C496.1 U37.AF12(SERDES2_TX1_N)
C_USB1_SS_TX_P: C495.1 U37.AG11(SERDES2_TX1_P)
CSI0_RX0_N: U37.B19(CSI0_RXN0) ; also on sheet 31
CSI0_RX0_P: U37.A20(CSI0_RXP0) ; also on sheet 31
CSI0_RX1_N: U37.D18(CSI0_RXN1) ; also on sheet 31
CSI0_RX1_P: U37.C19(CSI0_RXP1) ; also on sheet 31
CSI0_RX2_N: U37.D17(CSI0_RXN2) ; also on sheet 31
CSI0_RX2_P: U37.C18(CSI0_RXP2) ; also on sheet 31
CSI0_RX3_N: U37.E16(CSI0_RXN3) ; also on sheet 31
CSI0_RX3_P: U37.E17(CSI0_RXP3) ; also on sheet 31
CSI0_RXCLK_N: U37.B20(CSI0_RXCLKN) ; also on sheet 31
CSI0_RXCLK_P: U37.A21(CSI0_RXCLKP) ; also on sheet 31
CSI0_RXRCALIB: R366.1 U37.F16(CSI0_RXRCALIB)
CSI1_RXRCALIB: R358.1 U37.F15(CSI1_RXRCALIB)
DDR0_CAL0: R356.1 U37.H2(DDR0_CAL0)
DP0_AUX_N: C401.2 ; also on sheet 29
DP0_AUX_P: C402.2 ; also on sheet 29
DP0_TX0_N: C427.2 ; also on sheet 29
DP0_TX0_P: C428.2 ; also on sheet 29
DP0_TX1_N: C411.2 ; also on sheet 29
DP0_TX1_P: C412.2 ; also on sheet 29
DP0_TX2_N: C425.2 ; also on sheet 29
DP0_TX2_P: C426.2 ; also on sheet 29
DP0_TX3_N: C413.2 ; also on sheet 29
DP0_TX3_P: C414.2 ; also on sheet 29
DSI0_TX0_N: U37.D11(DSI_TXN0) ; also on sheet 30
DSI0_TX0_P: U37.C12(DSI_TXP0) ; also on sheet 30
DSI0_TX1_N: U37.D12(DSI_TXN1) ; also on sheet 30
DSI0_TX1_P: U37.C13(DSI_TXP1) ; also on sheet 30
DSI0_TX2_N: U37.B13(DSI_TXN2) ; also on sheet 30
DSI0_TX2_P: U37.A14(DSI_TXP2) ; also on sheet 30
DSI0_TX3_N: U37.B14(DSI_TXN3) ; also on sheet 30
DSI0_TX3_P: U37.A15(DSI_TXP3) ; also on sheet 30
DSI0_TXCLK_N: U37.E10(DSI_TXCLKN) ; also on sheet 30
DSI0_TXCLK_P: U37.E11(DSI_TXCLKP) ; also on sheet 30
DSI_TX_CALIB: R361.1 U37.F12(DSI_TXRCALIB)
ENET_EN: U37.T27(MMC2_DAT1) ; also on sheet 37
H_DDR_RET_1V1: U37.P6(DDR_RET) ; also on sheet 24
H_MMC1_CLK: U37.P25(MMC1_CLK) ; also on sheet 36
H_MMC1_CMD: U37.R29(MMC1_CMD) ; also on sheet 36
H_MMC1_D0: U37.R24(MMC1_DAT0) ; also on sheet 36
H_MMC1_D1: U37.P24(MMC1_DAT1) ; also on sheet 36
H_MMC1_D2: U37.R25(MMC1_DAT2) ; also on sheet 36
H_MMC1_D3: U37.R26(MMC1_DAT3) ; also on sheet 36
H_MMC1_SDCD: U37.P23(MMC1_SDCD) ; also on sheet 36
I2C3_SCL: R121.2 U37.T26(MMC2_CLK) ; also on sheet 32
I2C3_SDA: R118.2 U37.T25(MMC2_CMD) ; also on sheet 32
LPDDR4_CA0: U37.G4(DDR0_CA0) U40.H2(CA0_A) U40.R2(CA0_B)
LPDDR4_CA1: U37.H3(DDR0_CA1) U40.J2(CA1_A) U40.P2(CA1_B)
LPDDR4_CA2: U37.K5(DDR0_CA2) U40.H9(CA2_A) U40.R9(CA2_B)
LPDDR4_CA3: U37.J4(DDR0_CA3) U40.H10(CA3_A) U40.R10(CA3_B)
LPDDR4_CA4: U37.K2(DDR0_CA4) U40.H11(CA4_A) U40.R11(CA4_B)
LPDDR4_CA5: U37.H5(DDR0_CA5) U40.J11(CA5_A) U40.P11(CA5_B)
LPDDR4_CK_C: U37.J1(DDR0_CKN) U40.J9(CK_C_A) U40.P9(CK_C_B)
LPDDR4_CK_T: U37.H1(DDR0_CKP) U40.J8(CK_T_A) U40.P8(CK_T_B)
LPDDR4_CKE0: U37.G3(DDR0_CKE0) U40.J4(CKE0_A) U40.P4(CKE0_B)
LPDDR4_CKE1: U37.J3(DDR0_CKE1) U40.J5(CKE1_A) U40.P5(CKE1_B)
LPDDR4_CSN0_0: U37.J5(DDR0_CSN0_0) U40.H4(CS0_A)
LPDDR4_CSN0_1: U37.K3(DDR0_CSN0_1) U40.R4(CS0_B)
LPDDR4_CSN1_0: U37.G5(DDR0_CSN1_0) U40.H3(CS1_A)
LPDDR4_CSN1_1: U37.J2(DDR0_CSN1_1) U40.R3(CS1_B)
LPDDR4_DM0_DBI0#: U37.A3(DDR0_DM0) U40.C3(DMI0_A)
LPDDR4_DM1_DBI1#: U37.E4(DDR0_DM1) U40.C10(DMI1_A)
LPDDR4_DM2_DBI2#: U37.N1(DDR0_DM2) U40.Y3(DMI0_B)
LPDDR4_DM3_DBI3#: U37.R5(DDR0_DM3) U40.Y10(DMI1_B)
LPDDR4_DQ0: U37.A5(DDR0_DQ0) U40.B2(DQ0_A)
LPDDR4_DQ1: U37.A6(DDR0_DQ1) U40.C2(DQ1_A)
LPDDR4_DQ2: U37.B5(DDR0_DQ2) U40.E2(DQ2_A)
LPDDR4_DQ3: U37.C2(DDR0_DQ3) U40.F2(DQ3_A)
LPDDR4_DQ4: U37.B4(DDR0_DQ4) U40.F4(DQ4_A)
LPDDR4_DQ5: U37.C3(DDR0_DQ5) U40.E4(DQ5_A)
LPDDR4_DQ6: U37.A2(DDR0_DQ6) U40.C4(DQ6_A)
LPDDR4_DQ7: U37.A4(DDR0_DQ7) U40.B4(DQ7_A)
LPDDR4_DQ8: U37.D1(DDR0_DQ8) U40.B11(DQ8_A)
LPDDR4_DQ9: U37.C4(DDR0_DQ9) U40.C11(DQ9_A)
LPDDR4_DQ10: U37.F1(DDR0_DQ10) U40.E11(DQ10_A)
LPDDR4_DQ11: U37.G2(DDR0_DQ11) U40.F11(DQ11_A)
LPDDR4_DQ12: U37.F2(DDR0_DQ12) U40.F9(DQ12_A)
LPDDR4_DQ13: U37.F3(DDR0_DQ13) U40.E9(DQ13_A)
LPDDR4_DQ14: U37.D3(DDR0_DQ14) U40.C9(DQ14_A)
LPDDR4_DQ15: U37.F5(DDR0_DQ15) U40.B9(DQ15_A)
LPDDR4_DQ16: U37.L5(DDR0_DQ16) U40.AA2(DQ0_B)
LPDDR4_DQ17: U37.M5(DDR0_DQ17) U40.Y2(DQ1_B)
LPDDR4_DQ18: U37.N5(DDR0_DQ18) U40.V2(DQ2_B)
LPDDR4_DQ19: U37.L4(DDR0_DQ19) U40.U2(DQ3_B)
LPDDR4_DQ20: U37.L2(DDR0_DQ20) U40.U4(DQ4_B)
LPDDR4_DQ21: U37.L1(DDR0_DQ21) U40.V4(DQ5_B)
LPDDR4_DQ22: U37.N2(DDR0_DQ22) U40.Y4(DQ6_B)
LPDDR4_DQ23: U37.N4(DDR0_DQ23) U40.AA4(DQ7_B)
LPDDR4_DQ24: U37.T3(DDR0_DQ24) U40.AA11(DQ8_B)
LPDDR4_DQ25: U37.T2(DDR0_DQ25) U40.Y11(DQ9_B)
LPDDR4_DQ26: U37.P2(DDR0_DQ26) U40.V11(DQ10_B)
LPDDR4_DQ27: U37.P3(DDR0_DQ27) U40.U11(DQ11_B)
LPDDR4_DQ28: U37.P5(DDR0_DQ28) U40.U9(DQ12_B)
LPDDR4_DQ29: U37.R4(DDR0_DQ29) U40.V9(DQ13_B)
LPDDR4_DQ30: U37.T4(DDR0_DQ30) U40.Y9(DQ14_B)
LPDDR4_DQ31: U37.T5(DDR0_DQ31) U40.AA9(DQ15_B)
LPDDR4_DQS0_N: U37.B1(DDR0_DQS0N) U40.E3(DQS0_C_A)
LPDDR4_DQS0_P: U37.B2(DDR0_DQS0P) U40.D3(DQS0_T_A)
LPDDR4_DQS1_N: U37.E2(DDR0_DQS1N) U40.E10(DQS1_C_A)
LPDDR4_DQS1_P: U37.E3(DDR0_DQS1P) U40.D10(DQS1_T_A)
LPDDR4_DQS2_N: U37.M2(DDR0_DQS2N) U40.V3(DQS0_C_B)
LPDDR4_DQS2_P: U37.M3(DDR0_DQS2P) U40.W3(DQS0_T_B)
LPDDR4_DQS3_N: U37.R1(DDR0_DQS3N) U40.V10(DQS1_C_B)
LPDDR4_DQS3_P: U37.R2(DDR0_DQS3P) U40.W10(DQS1_T_B)
LPDDR4_ODT_CA_A: R359.1 R365.2 U40.G2(ODT_CA_A)
LPDDR4_ODT_CA_B: R349.1 R352.2 U40.T2(ODT_CA_B)
LPDDR4_RST#: R353.1 U37.K6(DDR0_RESETN) U40.T11(RESET_N)
LPDDR4_ZQ0: R373.2 U40.A5(ZQ0)
LPDDR4_ZQ1: R374.2 U40.A8(ZQ1)
MMC0_CALPAD: R331.2 U37.AE1(MMC0_CALPAD)
MMC0_CLK: R119.2 ; also on sheet 27
MMC0_CMD: U37.AE3(MMC0_CMD) ; also on sheet 27
MMC0_DAT0: U37.AG2(MMC0_DAT0) ; also on sheet 27
MMC0_DAT1: U37.AH1(MMC0_DAT1) ; also on sheet 27
MMC0_DAT2: U37.AG3(MMC0_DAT2) ; also on sheet 27
MMC0_DAT3: U37.AF4(MMC0_DAT3) ; also on sheet 27
MMC0_DAT4: U37.AE5(MMC0_DAT4) ; also on sheet 27
MMC0_DAT5: U37.AF3(MMC0_DAT5) ; also on sheet 27
MMC0_DAT6: U37.AG1(MMC0_DAT6) ; also on sheet 27
MMC0_DAT7: U37.AF2(MMC0_DAT7) ; also on sheet 27
MMC0_DS: U37.AE4(MMC0_DS) ; also on sheet 27
NEO_TIMEPULSE: U37.T24(MMC2_DAT0) ; also on sheet 39
PCIE0_REFCLK_N: R328.1 U37.AE17(PCIE_REFCLK0N) ; also on sheet 38
PCIE0_REFCLK_P: R338.1 U37.AD16(PCIE_REFCLK0P) ; also on sheet 38
PCIe0_RX0_N: U37.AH19(SERDES0_RX0_N) ; also on sheet 38
PCIe0_RX0_P: U37.AJ18(SERDES0_RX0_P) ; also on sheet 38
PCIe0_TX0_N: C509.2 ; also on sheet 38
PCIe0_TX0_P: C510.2 ; also on sheet 38
SERDES0_REXT: R334.1 U37.AE18(SERDES0_REXT)
SERDES1_REXT: R333.1 U37.AE13(SERDES1_REXT)
SERDES2_REXT: R341.1 U37.AD13(SERDES2_REXT)
SERDES3_REXT: R332.1 U37.AE8(SERDES3_REXT)
SERDES4_REXT: R360.1 U37.F9(SERDES4_REXT)
USB0_SS_RX2_N: U37.AH9(SERDES3_RX0_N) ; also on sheet 28
USB0_SS_RX2_P: U37.AJ8(SERDES3_RX0_P) ; also on sheet 28
USB0_SS_TX2_N: C494.2 ; also on sheet 28
USB0_SS_TX2_P: C493.2 ; also on sheet 28
USB1_SS_RX1_N: U37.AH12(SERDES2_RX1_N) ; also on sheet 28
USB1_SS_RX1_P: U37.AJ11(SERDES2_RX1_P) ; also on sheet 28
USB1_SS_TX1_N: C496.2 ; also on sheet 28
USB1_SS_TX1_P: C495.2 ; also on sheet 28
N29500526: R119.1 U37.AF1(MMC0_CLK)

Not connected (* = marked no-connect by the designer): U37 A17(CSI1_RXP0)* A18(CSI1_RXCLKP)* AC1(MLB0_MLBSN)* AC3(MLB0_MLBDP)* AD1(MLB0_MLBSP)* AD2(MLB0_MLBCP)* AD3(MLB0_MLBDN)* AD4(MMC0_VCTRL_TP)* AD6(UFS0_RSTN) AD10(PCIE_REFCLK3P)* AD12(PCIE_REFCLK2P)* AD15(PCIE_REFCLK1P)* AE2(MLB0_MLBCN)* AE6(UFS0_REF_CLK) AE9(PCIE_REFCLK3N)* AE11(PCIE_REFCLK2N)* AE14(PCIE_REFCLK1N)* AF6(UFS0_TX_DP1) AF7(UFS0_TX_DP0) AF10(SERDES3_TX1_N)* AF13(SERDES2_TX0_N)* AF15(SERDES1_TX0_N)* AF16(SERDES1_TX1_N)* AF18(SERDES0_TX1_N)* AG5(UFS0_TX_DN1) AG6(UFS0_TX_DN0) AG9(SERDES3_TX1_P)* AG12(SERDES2_TX0_P)* AG14(SERDES1_TX0_P)* AG15(SERDES1_TX1_P)* AG17(SERDES0_TX1_P)* AH3(UFS0_RX_DN0) AH4(UFS0_RX_DN1) AH10(SERDES3_RX1_N)* AH13(SERDES2_RX0_N)* AH15(SERDES1_RX0_N)* AH16(SERDES1_RX1_N)* AH18(SERDES0_RX1_N)* AJ2(UFS0_RX_DP0) AJ3(UFS0_RX_DP1) AJ9(SERDES3_RX1_P)* AJ12(SERDES2_RX0_P)* AJ14(SERDES1_RX0_P)* AJ15(SERDES1_RX1_P)* AJ17(SERDES0_RX1_P)* B16(CSI1_RXN0)* B17(CSI1_RXCLKN)* C6(SERDES4_RX3_P)* C7(SERDES4_RX2_P)* C9(SERDES4_RX1_P)* C10(SERDES4_RX0_P)* C15(CSI1_RXP2)* C16(CSI1_RXP1)* D5(SERDES4_RX3_N)* D6(SERDES4_RX2_N)* D8(SERDES4_RX1_N)* D9(SERDES4_RX0_N)* D14(CSI1_RXN2)* D15(CSI1_RXN1)* E6(DP0_AUX_ATB_1)* E7(SERDES4_REFCLK_N)* E8(SERDES4_REFCLK_P)* E13(CSI1_RXN3)* E14(CSI1_RXP3)* E18(CSI0_ATB_0_H)* F6(DP0_AUX_ATB_0)* F10(DSI_ATB_1_H)* F11(CSI1_ATB_1_H)* F18(CSI0_ATB_1_H)* G9(DSI_ATB_0_H)* G10(CSI1_ATB_0_H)* L6(DDR0_ATB1)* N6(DDR0_ATB0)* R28(MMC1_SDWP); U40 A1(DNU1)* A2(DNU2)* A11(DNU3)* A12(DNU4)* AA1(DNU7)* AA12(DNU8)* AB1(DNU9)* AB2(DNU10)* AB11(DNU11)* AB12(DNU12)* B1(DNU5)* B12(DNU6)* G11(NC1)* K5(NC2)* K8(NC3)* N5(NC4)* N8(NC5)*

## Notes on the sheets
sheet 1
- Sheet # - Name
  =====================================
  01. TITLE PAGE
  02. EVM REVISION HISTORY
  03. SYSTEM BLOCK DGM
  04. POWER DGM
  05. PMIC DGM
  06. I2C ADDR TABLE
  07. SOC GPIO_MAPPING_TABLE
  08. SOC MLB, CSI & DSI IF
  09. SOC SERDES IF
  10. SOC MMC & UFS IF
  11. SOC EMIF & LPDDR4
  12. SOC MCU FLASH
  13. SOC RGMII, ADC
  14. SOC MCU & MAIN GEN IO, OSC
  15. SOC GENERAL & USB
  16. SOC PRG0 & PRG1
  17. SOC ANALOG POWER 1
  18. SOC DIGITAL POWER 2
  19. SOC DIGITAL POWER 3
  20. SOC GND
  21. POWER LM5176
  22. POWER LM5141
  23. PMIC A
  24. PMIC B
  25. LOAD SWITCHES
  26. SECONDARY LDO'S/SWITCHES
  27. BOOTMODE SWITCH
  28. MEM eMMC
  29. USB MEDIA
  30. DISPLAY PORT INTERFACE
  31. DSI-FPD_LINK
  32. ENET/CAN
  33. CSI2 CAMERA
  34. USB HUB/WIFI
  35. AUDIO OUT
  36. AUDIO IN
  37. EXPANSION/GNSS
  38. DEBUG
  39. TUNER
  40. DEBUG SDCARD
  =====================================
- REV
- DESCRIPTION
- DATE
- Author
- A
- INITIAL CAPTURE
- 10/29/2019
- JAC
- A1
- REV A BOARD BRING UP CHANGES
- 12/18/2019
- JAC
- B
- REV B BOARD BRING UP CHANGES
- 12/20/2019
- JAC
- *** DISCLAIMER ***
  The SoC Reference Design Study provides SCH & PCB source files that can be used
  as a good starting point for new designs. Please be aware that the SCH & PCB
  are NOT 100% complete for implementing an End Product.  An End Product's
  feature set will define additional required signaling and SoC interfaces. As a result,
  a majority of signals in this SCH are "single-pin" / "unconnected" nets.
  The SoC's schematic symbol has been organized based upon each ball's "primary
  signaling interface". For End Products, unused primary interface signals can then be re-defined
  by SoC's internal muxmode controll (see Data Manual for details) to use "alternate functions"
  (i.e. GPIOs) to support other key system needs (i.e. interupts, debug, etc.).
  Primary objectives of this Ref Design are to demonstrate:
    1. 100% signal & power breakout routing of SoC using recommended PCB design rules & strategies.
    2. Key high-speed signals with controlled impedance PCB routing (i.e. DDR & SERDES).
    3. Power Distribution Network (PDN) with the following:
       a) Recommended SoC power solution components (2nd stage) showing preferred SoC voltage domain
           to power resource mapping.
       b) Optimized decoupling capacitor scheme per key power rail using only automotive qualified caps
           to meet SoC recommended power integrity (PI) parameters based on this specific
           PCB design (stack-up, placement, routing, via types, etc).
       c.) A typical 1st stage power conversion interfaced directly to input battery has been captured as
           an example.
- REVISION STATUS OF SHEETS
- REV
- A
- B
- B
- A
- A
- A
- A
- A
- A
- A
- DWN
- DATE
- SH
- 31
- 32
- 33
- 34
- 35
- 36
- 37
- 38
- 39
- 40
- J.A.C.
- 10/29/2019
- CHK
- DATE
- REV
- A
- A
- A
- A
- A
- A
- A
- A
- A
- B
- T.W.K.
- 10/29/2019
- SH
- 21
- 22
- 23
- 24
- 25
- 26
- 27
- 28
- 29
- 30
- ENGR
- J.A.C.
- 10/29/2019
- DATE
- ENGR-MGR
- DATE
- REV
- A
- B
- A
- A
- A
- A
- A
- A
- A
- A
- J.A.C.
- 10/29/2019
- QA
- DATE
- SH
- 11
- 12
- 13
- 14
- 15
- 16
- 17
- 18
- 19
- 20
- C.M.D.
- 10/29/2019
- MFG
- DATE
- REV
- B
- B
- A
- A
- A
- B
- B
- A
- A
- A
- NEXT ASSY
- USED ON
- RLSE
- J.A.C.
- 10/29/2019
- DATE
- SH
- 1
- 2
- 3
- 4
- 5
- 6
- 7
- 8
- 9
- 10
- APPLICATION
- J.A.C.
- 10/29/2019
sheet 2
- REVISION HISTORY
- DATE
- CHANGE
- AUTHOR
- REV B CHANGES
- 01/03/2020
- SHEET 6/7 UPDATE TABLES
- TNYC
- SHEET 12 NO-POP R186, MCU_OSPI1_LBCLKO AS GPIO
- SHEET 30 CON_DP0_AUX_N PULLUP TO 3V3
- SHEET 30 ISOLATE AND ESD PROTECT DPO_HPD
- SHEET 32 MIRROR MCU_MCAN1_RX/TX AT U44
- SHEET 33 MIRROR UB960 I2C6 SDA/SCL
- SHEET 19 DELETE C656, C661, C721, C729 TO
  MAKE ROOM FOR 3-T UNDER SOC.
- 02/24/2020
sheet 4
- CHANGE TO LM5176
sheet 6
- SoM I2C ADDRESS TABLE
sheet 7
- GPIO MAPPING TABLE
sheet 8
- MLB
- DSI
- Note:  ATB pins to be left unconnected
- CSI Interface
- Note:  ATB pins to be left unconnected
- Note:  ATB pins to be left unconnected
sheet 9
- SERDES
- Note: Place DC blocking caps near
  SOM Connector
- Note:  ATB pins to be left unconnected
sheet 10
- MMC Interface
- UFS Interface
sheet 11
- LPDDR4
- EMIF
- Dcap scheme needs improvement
  to reduce Zpk vs F (WiP)
